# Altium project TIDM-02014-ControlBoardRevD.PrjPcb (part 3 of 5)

## Sheet thermal-management.SchDoc: Thermal Management
size 431 x 279 mm; Date: Not shown in title block; ApprovedBy: Not shown in title block; CheckedBy: Not shown in title block; Author: Not shown in title block; CompanyName: Not shown in title block; DrawnBy: Panacek; Engineer: Not shown in title block; Organization: Not shown in title block; Address1: Not shown in title block; Address2: Not shown in title block; Address3: Not shown in title block; Address4: Not shown in title block; DocumentNumber: 9; Revision: Use project parameter SCH_Rev; SheetNumber: 11; SheetTotal: 19; PageSetup: Record=PageOptions¦CenterHorizontal=True¦CenterVertical=True¦PrintScale=1.00¦XCorrection=1.00¦YCorrection=1.00¦PrintKind=0¦BorderSize=5000000¦LeftOffset=0¦BottomOffset=0¦Orientation=2¦PaperLength=1000¦PaperWidth=1000¦Scale=100¦PaperSource=15¦PrintQuality=600¦MediaType=1¦DitherType=10¦PaperKind=Letter¦PrintScaleMode=1
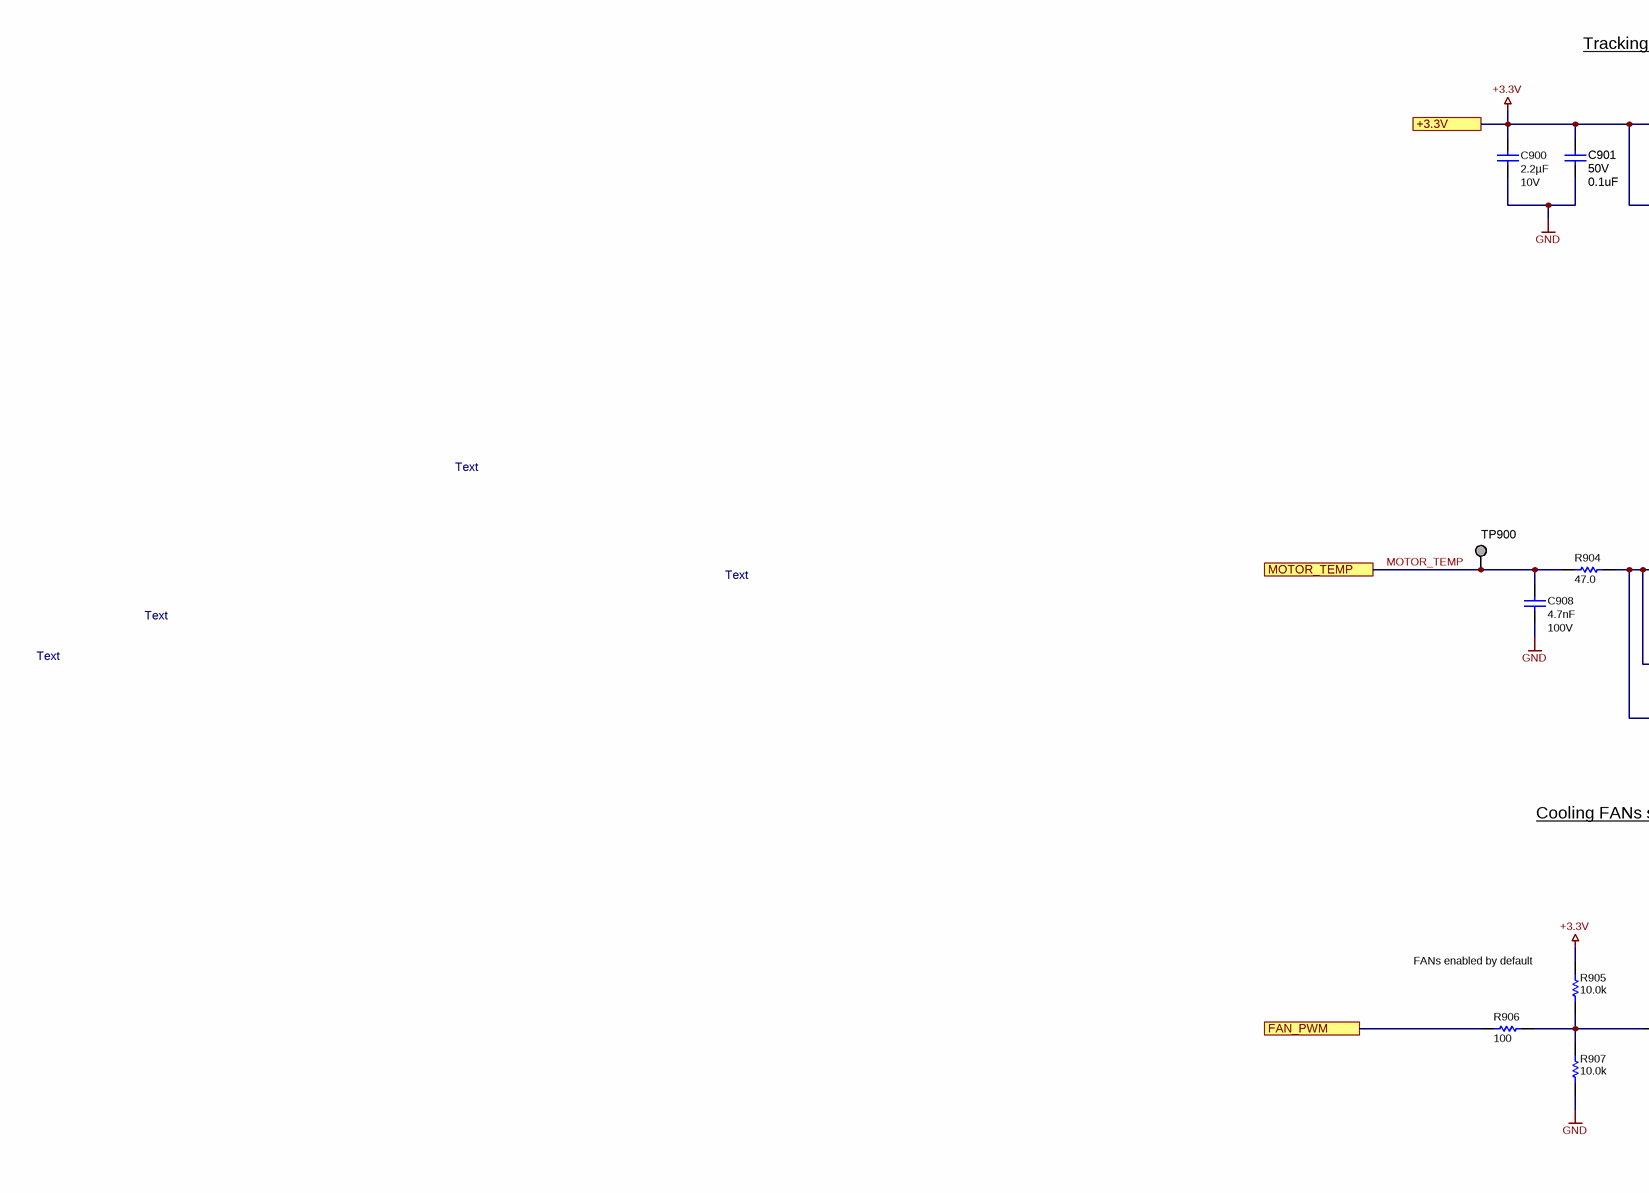
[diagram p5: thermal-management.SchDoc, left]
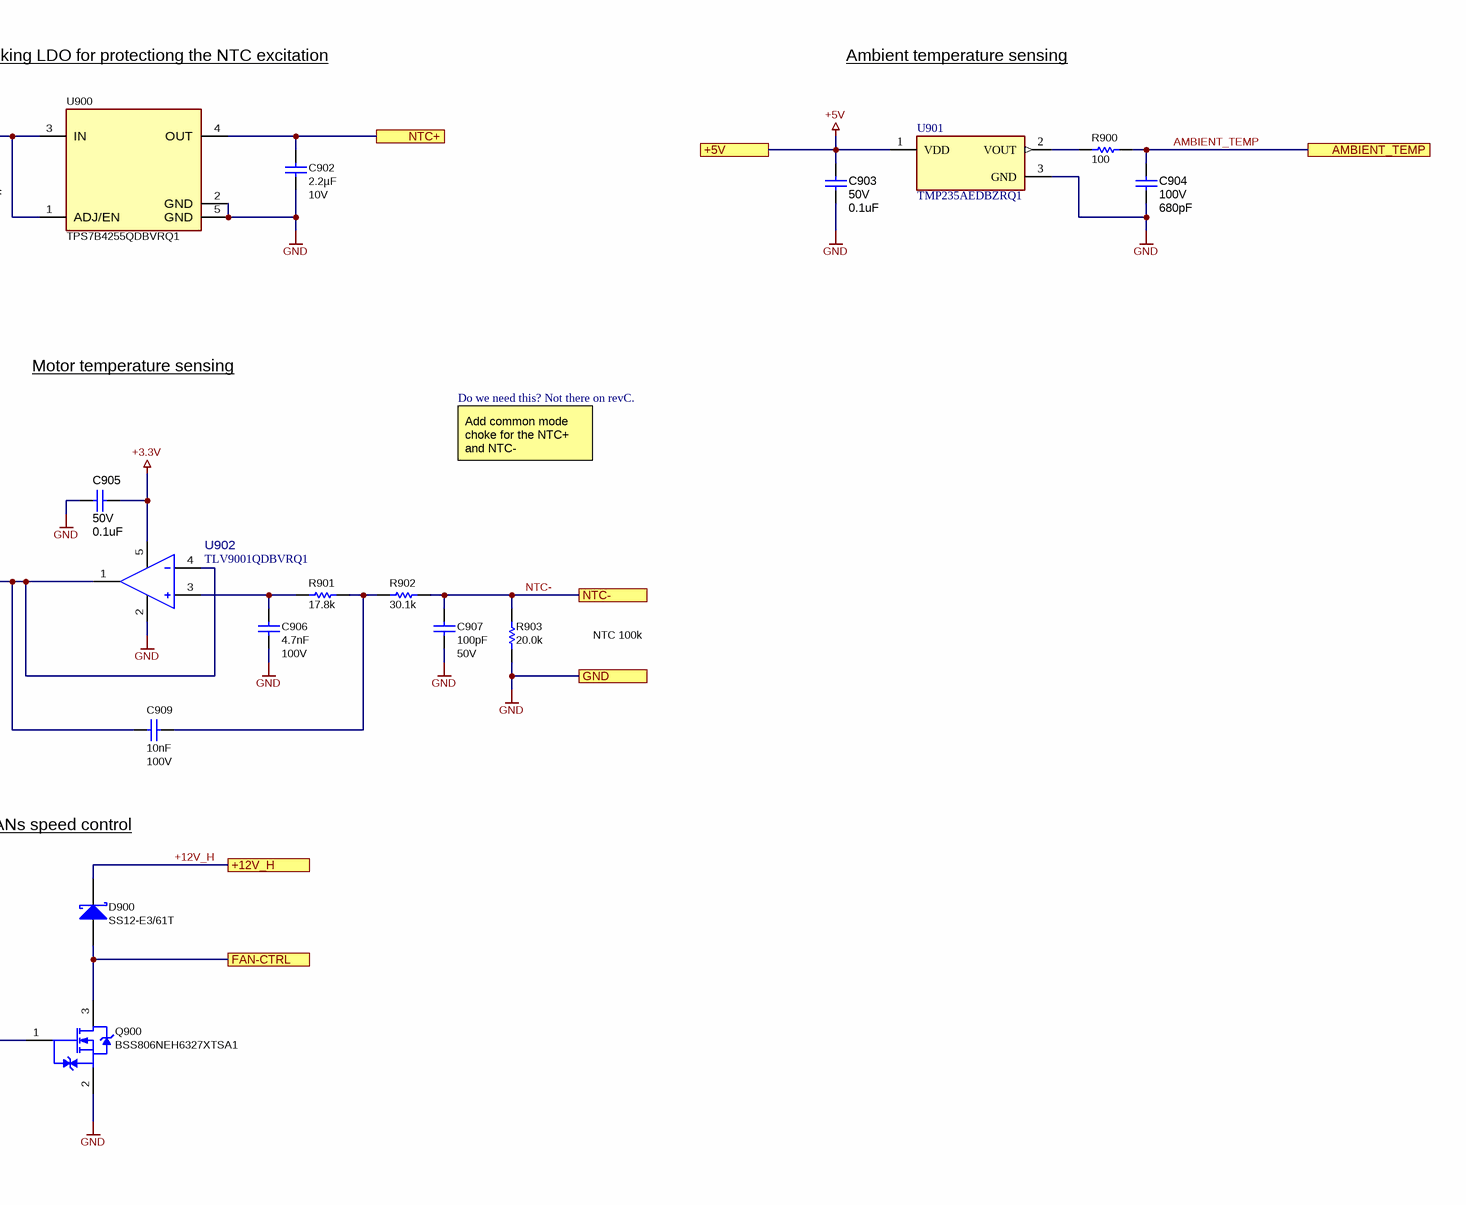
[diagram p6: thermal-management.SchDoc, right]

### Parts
C900  Cap_F: 2.2µF  VDC_V: 10V  [0603]  (hidden comment: GRM188R71A225KE15J)
C901  VDC_V: 50V  ValueDisplayed: 0.1uF  [0603]  (hidden comment: CGA3E2X7R1H104K080AA)
C902  Cap_F: 2.2µF  VDC_V: 10V  [0603]  (hidden comment: GRM188R71A225KE15J)
C903  VDC_V: 50V  ValueDisplayed: 0.1uF  [0603]  (hidden comment: CGA3E2X7R1H104K080AA)
C904  VDC_V: 100V  ValueDisplayed: 680pF  [0603]  (hidden comment: GRM188R72A681KA01D)
C905  VDC_V: 50V  ValueDisplayed: 0.1uF  [0603]  (hidden comment: CGA3E2X7R1H104K080AA)
C906  Cap_F: 4.7nF  VDC_V: 100V  [0603]  (hidden comment: GCM188R72A472KA37D)
C907  Cap_F: 100pF  VDC_V: 50V  [0603]  (hidden comment: CGA3E2NP01H101J080AA)
C908  Cap_F: 4.7nF  VDC_V: 100V  [0603]  (hidden comment: GCM188R72A472KA37D)
C909  Cap_F: 10nF  VDC_V: 100V  [0603]  (hidden comment: CGA3E2X7R2A103K080AA)
D900  SS12-E3/61T  [SMA]
Q900  BSS806NEH6327XTSA1  [SOT-23L]
R900  ValueDisplayed: 100  [0603]  (hidden comment: CRCW0603100RFKEA)
R901  ValueDisplayed: 17.8k  [0603]  (hidden comment: CRCW060317K8FKEA)
R902  ValueDisplayed: 30.1k  [0603]  (hidden comment: CRCW060330K1FKEA)
R903  ValueDisplayed: 20.0k  [0805_HV]  (hidden comment: CRCW080520K0FKEA)
R904  ValueDisplayed: 47.0  [0603]  (hidden comment: CRCW060347R0FKEA)
R905  ValueDisplayed: 10.0k  [0603]  (hidden comment: CRCW060310K0FKEA)
R906  ValueDisplayed: 100  [0603]  (hidden comment: CRCW0603100RFKEA)
R907  ValueDisplayed: 10.0k  [0603]  (hidden comment: CRCW060310K0FKEA)
TP900  RCU-0C  [TE_RCU]  (value not drawn)
U900  TPS7B4255QDBVRQ1  [DBV0005A-MFG]
U901  TMP235AEDBZRQ1  [FP-DBZ0003A-IPC_A]
U902  TLV9001QDBVRQ1  [DBV0005A-MFG]

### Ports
+3.3V, +5V, +12V_H, AMBIENT_TEMP, FAN-CTRL, FAN_PWM, GND, MOTOR_TEMP, NTC+, NTC-

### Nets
+3.3V: C900.1 C901.2 C905.2 R905.2 U900.1(ADJ/EN) U900.3(IN) U902.5(V+) ; port +3.3V
+5V: C903.1 U901.1(VDD) ; port +5V
+12V_H: D900.1(K) ; port +12V_H
GND: C900.2 C901.1 C902.2 C903.2 C904.2 C905.1 C906.2 C907.2 C908.2 Q900.2(S) R903.1 R907.1 U900.2(GND) U900.5(GND) U901.3(GND) U902.2(V-) ; port GND
AMBIENT_TEMP: C904.1 R900.2 ; port AMBIENT_TEMP
FAN-CTRL: D900.2(A) Q900.3(D) ; port FAN-CTRL
FAN_PWM: R906.1 ; port FAN_PWM
MOTOR_TEMP: C908.1 R904.1 TP900.1 ; port MOTOR_TEMP
NTC+: C902.1 U900.4(OUT) ; port NTC+
NTC-: C907.1 R902.2 R903.2 ; port NTC-
NetC906_1: C906.1 R901.1 U902.3(IN+)
NetC909_1: C909.1 R901.2 R902.1
NetC909_2: C909.2 R904.2 U902.1(OUT) U902.4(IN-)
NetQ900_1: Q900.1(G) R905.1 R906.2 R907.2
NetR900_1: R900.1 U901.2(VOUT)

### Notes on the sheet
- Tracking LDO for protectiong the NTC excitation
- Ambient temperature sensing
- Motor temperature sensing
- Do we need this? Not there on revC.
- Text
- Add common mode choke for the NTC+ and NTC-
- NTC 100k
- Cooling FANs speed control
- (near R905) FANs enabled by default

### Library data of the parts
C900 C902 = CMP-0084284-1: CAP, CERM, 2.2 µF, 10 V,+/- 10%, X7R, AEC-Q200 Grade 1, 0603; Manufacturer: MuRata; SizeAreaWB_mm2: 4.68; Polarized: N; AEC Qualified: Y; SizeX_mm: 1.6; SizeZ_mm: 1; SizeY_mm: 0.8; U/M: EA; TaMin_C: -55°C; Value: 2.2uF; AEC Category: Q200; TaMax_C: 125°C; SizeArea_mm2: 1.28
C901 C903 C905 = CMP-0007078-4: CAP, CERM, 0.1 uF, 50 V, +/- 10%, X7R, AEC-Q200 Grade 1, 0603; Manufacturer: TDK; TaMin_C: -55°C; Polarized: N; SizeAreaWB_mm2: 4.68; U/M: EA; Value: 0.1uF; TaMax_C: 125°C; SizeZ_mm: 1; SizeX_mm: 1.6; SizeY_mm: 0.8; SizeArea_mm2: 1.28; AEC Qualified: Y; Cap_F: 100nF; AEC Category: Q200; ESR_ohm: 29.6m; IRMS_A: 971.99mA; Value1: 0.0296 ohm
C904 = CMP-0007486-5: CAP, CERM, 680 pF, 100 V, +/- 10%, X7R, 0603; Manufacturer: MuRata; TaMin_C: -55°C; Polarized: N; SizeAreaWB_mm2: 4.68; Value1: Unknown; U/M: EA; Value: 680pF; TaMax_C: 125°C; SizeZ_mm: 1; SizeX_mm: 1.6; SizeY_mm: 0.8; SizeArea_mm2: 1.28; AEC Category: Q200
C906 C908 = CMP-0079247-1: CAP, CERM, 4700 pF, 100 V,+/- 10%, X7R, AEC-Q200 Grade 1, 0603; Manufacturer: MuRata; TaMin_C: -55°C; Polarized: N; SizeAreaWB_mm2: 4.68; U/M: EA; Value: 4700pF; TaMax_C: 125°C; SizeZ_mm: 1; SizeX_mm: 1.6; SizeY_mm: 0.8; SizeArea_mm2: 1.28; AEC Qualified: Y; AEC Category: Q200
C907 = CMP-0007075-4: CAP, CERM, 100 pF, 50 V, +/- 5%, C0G/NP0, AEC-Q200 Grade 0, 0603; Manufacturer: TDK; TaMin_C: -55°C; Polarized: N; SizeAreaWB_mm2: 4.68; Value1: Unknown; U/M: EA; Value: 100pF; TaMax_C: 150°C; SizeZ_mm: 1; SizeX_mm: 1.6; SizeY_mm: 0.8; SizeArea_mm2: 1.28; AEC Qualified: Y; AEC Grade: 0; AEC Category: Q200
C909 = CMP-0007082-4: CAP, CERM, 0.01 uF, 100 V, +/- 10%, X7R, AEC-Q200 Grade 1, 0603; Manufacturer: TDK; TaMin_C: -55°C; Polarized: N; SizeAreaWB_mm2: 4.68; Value1: 0.235428 ohm; U/M: EA; Value: 0.01uF; TaMax_C: 125°C; SizeZ_mm: 1; SizeX_mm: 1.6; SizeY_mm: 0.8; SizeArea_mm2: 1.28; AEC Qualified: Y; AEC Category: Q200; ESR_ohm: 0.2354; IRMS_A: 396.995mA
D900 = CMP-0028582-2: Diode, Schottky, 20 V, 1 A, SMA; Manufacturer: Vishay-Semiconductor; SizeZ_mm: 2.87; SizeX_mm: 5.59; Green_Lifecycle: Not Set; RJC_CperW: 28; Io_A: 1A; Green_REACh: Incomplete; Vr_V: 20V; AEC Category: Q101; TJmax_C: 125°C; Value2: 0.5V; SizeAreaWB_mm2: 37.3428; Value: 20V; SizeArea_mm2: 16.3228; Vf_V: 500mV; SizeY_mm: 2.92
Q900 = CMP-0077248-1: MOSFET, N-CH, 20 V, 2.3 A, AEC-Q101, SOT-23; Manufacturer: Infineon Technologies; Alternate Manufacturer: None; ChType: N; QgTyp_nC: 1.7; SizeAreaWB_mm2: 14.0; SizeArea_mm2: 7.5; IdsMax_A: 2.3A; AEC Qualified: Y; VdsMax_V: 20V; Vgs_V: 8V; AEC Category: Q101; Value: 20V; SizeZ_mm: 1.1; SizeY_mm: 3.0; Value2: 1.7 nC; U/M: EA; Value1: ? ohm; SizeX_mm: 2.5
R900 R906 = CMP-0021991-4: RES, 100, 1%, 0.1 W, AEC-Q200 Grade 0, 0603; Manufacturer: Vishay-Dale; Power_W: 100mW; TempCo: 100 ppm/C; Value_Code: 100R; Value: 100; EIA_Code: E96; SizeX_mm: 1.6; SizeY_mm: 0.8; SizeZ_mm: 1; Value2: 0.1W; SizeArea_mm2: 1.28; AEC Qualified: Y; VDC_V: 75V; AEC Category: Q200; AEC Grade: 0
R901 = CMP-0022090-4: RES, 17.8 k, 1%, 0.1 W, AEC-Q200 Grade 0, 0603; Manufacturer: Vishay-Dale; Power_W: 100mW; TempCo: 100 ppm/C; Value_Code: 17k8; Value: 17.8k; EIA_Code: E96; SizeX_mm: 1.6; SizeY_mm: 0.8; SizeZ_mm: 1; Value2: 0.1W; SizeArea_mm2: 1.28; AEC Qualified: Y; VDC_V: 75V; AEC Category: Q200; AEC Grade: 0
R902 = CMP-0022324-4: RES, 30.1 k, 1%, 0.1 W, AEC-Q200 Grade 0, 0603; Manufacturer: Vishay-Dale; Power_W: 100mW; TempCo: 100 ppm/C; Value_Code: 30k1; Value: 30.1k; EIA_Code: E96; SizeX_mm: 1.6; SizeY_mm: 0.8; SizeZ_mm: 1; Value2: 0.1W; SizeArea_mm2: 1.28; AEC Qualified: Y; VDC_V: 75V; AEC Category: Q200; AEC Grade: 0
R903 = CMP-0021042-3: RES, 20.0 k, 1%, 0.125 W, AEC-Q200 Grade 0, 0805; Manufacturer: Vishay-Dale; Power_W: 125mW; TempCo: 100 ppm/C; Value_Code: 20k0; Value: 20.0k; EIA_Code: E96; Res_ohm: 20k; SizeX_mm: 2; SizeY_mm: 1.25; SizeZ_mm: 1.45; Value2: 0.125W; SizeArea_mm2: 2.5; AEC Qualified: Y; VDC_V: 150V; AEC Category: Q200; AEC Grade: 0
R904 = CMP-0081280-1: RES, 47.0, 1%, 0.1 W, AEC-Q200 Grade 0, 0603; Manufacturer: Vishay-Dale; Value: 47.0; Res_ohm: 47; Value_Code: 47R0; Power_W: 100mW; Value2: 0.1W; VDC_V: 75V; TempCo: 100 ppm/C; SizeArea_mm2: 1.28; SizeX_mm: 1.6; SizeY_mm: 0.8; SizeZ_mm: 1; AEC Category: Q200; AEC Qualified: Y; AEC Grade: 0; SizeAreaWB_mm2: 4.68
R905 R907 = CMP-0021998-4: RES, 10.0 k, 1%, 0.1 W, AEC-Q200 Grade 0, 0603; Manufacturer: Vishay-Dale; Power_W: 100mW; TempCo: 100 ppm/C; Value_Code: 10k0; Value: 10.0k; EIA_Code: E96; Res_ohm: 10k; SizeX_mm: 1.6; SizeY_mm: 0.8; SizeZ_mm: 1; Value2: 0.1W; SizeArea_mm2: 1.28; AEC Qualified: Y; VDC_V: 75V; AEC Category: Q200; AEC Grade: 0
TP900 = CMP-0067620-1: PC Test Point, SMT; Manufacturer: TE Connectivity
U900 = CMP-0096536-1: Automotive, 70-mA, 40-V, Voltage-Tracking LDO With 5-mV Tracking Tolerance, SOT23-5; Manufacturer: Texas Instruments; SizeZ_mm: 1.45mm; Standoff Height: 0mm; Max Supply Voltage: 40V; TaMax_C: +125°C; Dropout Voltage: 500mV; AEC Qualified: Yes; Min Supply Voltage: 3V; Output Voltage: 2-40V; AEC Grade: Grade 1; Nominal Supply Current: 600-800uA; Number Of Outputs: 1; TaMin_C: -40°C; TJmax_C: +150°C; Output Type: AdjustableProgrammable
U901 = CMP-04948-000108-1: IC TEMP SENSOR; Manufacturer: Texas Instruments
U902 = CMP-0120546-1: Automotive, single-channel, 5.5-V 1-MHz rail-to-rail input and output operational amplifier 5-SOT-23 -40 to 125; Manufacturer: Texas Instruments; SizeZ_mm: 1.45mm; AEC Qualified: Yes; AEC Grade: Grade 1; Gain Bandwidth: 1MHz; Input Bias Current: 0.000005uA; Input Offset Voltage: 0.4mV; Max Dual Supply Voltage: 2.75V; Max Supply Voltage: 5.5V; Min Dual Supply Voltage: 900mV; Min Supply Voltage: 1.8V; Nominal Supply Current: 60uA; Number Of Channels: 1; Output Current Per Channel: 40mA; Response Time: 3us; Standoff Height: 0mm; TaMax_C: +125°C; TaMin_C: -40°C; TJmax_C: +150°C; Voltage Gain: 130dB

## Sheet hardware.SchDoc: Hardaware / Mechanical
size 431 x 279 mm; Date: Not shown in title block; ApprovedBy: Not shown in title block; CheckedBy: Not shown in title block; Author: Not shown in title block; CompanyName: Not shown in title block; DrawnBy: Panacek; Engineer: Not shown in title block; Organization: Not shown in title block; Address1: Not shown in title block; Address2: Not shown in title block; Address3: Not shown in title block; Address4: Not shown in title block; DocumentNumber: 12; Revision: Use project parameter SCH_Rev; SheetNumber: 14; SheetTotal: 19; PageSetup: Record=PageOptions¦CenterHorizontal=True¦CenterVertical=True¦PrintScale=1.00¦XCorrection=1.00¦YCorrection=1.00¦PrintKind=0¦BorderSize=5000000¦LeftOffset=0¦BottomOffset=0¦Orientation=2¦PaperLength=1000¦PaperWidth=1000¦Scale=100¦PaperSource=15¦PrintQuality=600¦MediaType=1¦DitherType=10¦PaperKind=Letter¦PrintScaleMode=1
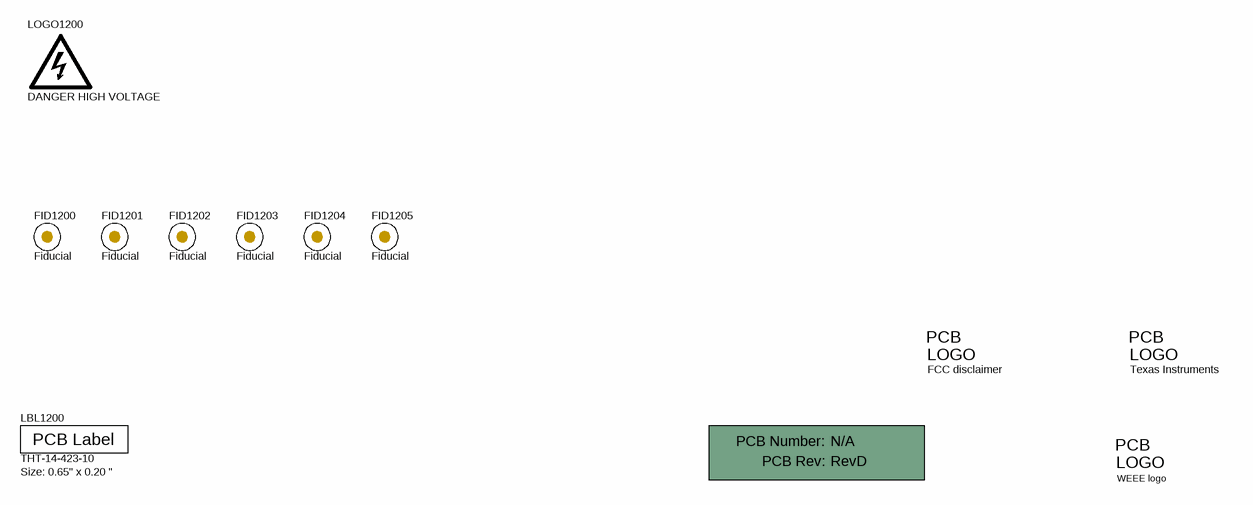
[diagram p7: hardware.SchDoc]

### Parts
!PCB1200  Printed Circuit Board  (value not drawn)  (mechanical)
FID1200  Fiducial  [Fiducial10-20]
FID1201  Fiducial  [Fiducial10-20]
FID1202  Fiducial  [Fiducial10-20]
FID1203  Fiducial  [Fiducial10-20]
FID1204  Fiducial  [Fiducial10-20]
FID1205  Fiducial  [Fiducial10-20]
LBL1200  THT-14-423-10  Note: Size: 0.65" x 0.20 "  [Label_650x200]
LOGO1200  DANGER HIGH VOLTAGE  [IEC_HighVoltage_Large]  (no BOM)
Logo1201  FCC disclaimer  [FCC_disclaimer]  (no BOM)
Logo1202  Texas Instruments  [TI_Stacked_Overlay_Small]  (no BOM)
Logo1203  WEEE logo  [WEEE_Minimum]  (no BOM)

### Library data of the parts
!PCB1200 = CMP-0003618-2: Manufacturer: Any
FID1200-FID1205 = CMP-0077181-1: Fiducial mark.  There is nothing to buy or mount.
LBL1200 = CMP-0003625-1: Thermal Transfer Printable Labels, 0.650" W x 0.200" H - 10,000 per roll; Manufacturer: Brady
LOGO1200 = CMP-0074835-1: IEC 61010-1 High Voltage Warning; SymbolCreator: a0412235
Logo1201 = CMP-0074847-1: FCC_disclaimer
Logo1202 = CMP-0074838-1: Texas Instrument Corporate Signature; SymbolCreator: a0412235; Lib Reference: TI_Logo
Logo1203 = CMP-0074769-1

## Sheet eqep_ecap_interface.SchDoc: EQEO/ECAP Inaterface
size 431 x 279 mm; Date: Not shown in title block; ApprovedBy: Not shown in title block; CheckedBy: Not shown in title block; Author: Not shown in title block; CompanyName: Not shown in title block; DrawnBy: Panacek; Engineer: Not shown in title block; Organization: Not shown in title block; Address1: Not shown in title block; Address2: Not shown in title block; Address3: Not shown in title block; Address4: Not shown in title block; DocumentNumber: 11; Revision: Use project parameter SCH_Rev; SheetNumber: 13; SheetTotal: 19; PageSetup: Record=PageOptions¦CenterHorizontal=True¦CenterVertical=True¦PrintScale=1.00¦XCorrection=1.00¦YCorrection=1.00¦PrintKind=0¦BorderSize=5000000¦LeftOffset=0¦BottomOffset=0¦Orientation=2¦PaperLength=1000¦PaperWidth=1000¦Scale=100¦PaperSource=15¦PrintQuality=600¦MediaType=1¦DitherType=10¦PaperKind=Letter¦PrintScaleMode=1
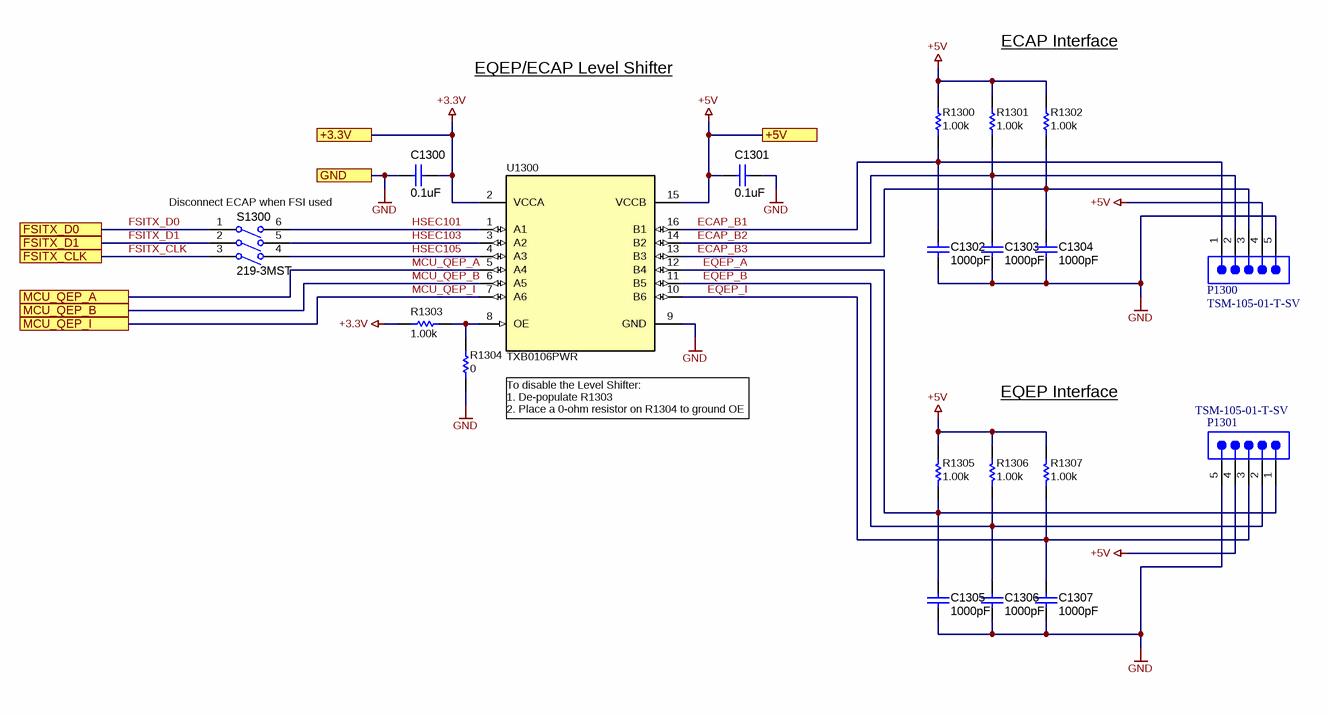
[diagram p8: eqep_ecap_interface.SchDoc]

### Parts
C1300  ValueDisplayed: 0.1uF  [0603]  (hidden comment: CGA3E2X7R1H104K080AA)
C1301  ValueDisplayed: 0.1uF  [0603]  (hidden comment: CGA3E2X7R1H104K080AA)
C1302  ValueDisplayed: 1000pF  [0603]  (hidden comment: GRM1885C1H102JA01D)
C1303  ValueDisplayed: 1000pF  [0603]  (hidden comment: GRM1885C1H102JA01D)
C1304  ValueDisplayed: 1000pF  [0603]  (hidden comment: GRM1885C1H102JA01D)
C1305  ValueDisplayed: 1000pF  [0603]  (hidden comment: GRM1885C1H102JA01D)
C1306  ValueDisplayed: 1000pF  [0603]  (hidden comment: GRM1885C1H102JA01D)
C1307  ValueDisplayed: 1000pF  [0603]  (hidden comment: GRM1885C1H102JA01D)
P1300  TSM-105-01-T-SV  [SMTC-TSM-105-01-X-SV]
P1301  TSM-105-01-T-SV  [SMTC-TSM-105-01-X-SV]
R1300  ValueDisplayed: 1.00k  [0603]  (hidden comment: CRCW06031K00FKEA)
R1301  ValueDisplayed: 1.00k  [0603]  (hidden comment: CRCW06031K00FKEA)
R1302  ValueDisplayed: 1.00k  [0603]  (hidden comment: CRCW06031K00FKEA)
R1303  ValueDisplayed: 1.00k  [0603]  (hidden comment: CRCW06031K00FKEA)
R1304  ValueDisplayed: 0  [0603]  (hidden comment: CRCW06030000Z0EA)
R1305  ValueDisplayed: 1.00k  [0603]  (hidden comment: CRCW06031K00FKEA)
R1306  ValueDisplayed: 1.00k  [0603]  (hidden comment: CRCW06031K00FKEA)
R1307  ValueDisplayed: 1.00k  [0603]  (hidden comment: CRCW06031K00FKEA)
S1300  219-3MST  [SW_219-3MST]
U1300  TXB0106PWR  [PW0016A_N]

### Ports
+3.3V, +5V, FSITX_CLK, FSITX_D0, FSITX_D1, GND, MCU_QEP_A, MCU_QEP_B, MCU_QEP_I

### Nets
+3.3V: C1300.1 R1303.1 U1300.2(VCCA) ; port +3.3V
+5V: C1301.2 P1300.4 P1301.4 R1300.2 R1301.2 R1302.2 R1305.2 R1306.2 R1307.2 U1300.15(VCCB) ; port +5V
GND: C1300.2 C1301.1 C1302.2 C1303.2 C1304.2 C1305.2 C1306.2 C1307.2 P1300.5 P1301.5 R1304.1 U1300.9(GND) ; port GND
ECAP_B1: C1302.1 P1300.1 R1300.1 U1300.16(B1)  [project net ECAP_B1_13]
ECAP_B2: C1303.1 P1300.2 R1301.1 U1300.14(B2)  [project net ECAP_B2_13]
ECAP_B3: C1304.1 P1300.3 R1302.1 U1300.13(B3)  [project net ECAP_B3_13]
EQEP_A: C1305.1 P1301.1 R1305.1 U1300.12(B4)  [project net EQEP_A_13]
EQEP_B: C1306.1 P1301.2 R1306.1 U1300.11(B5)  [project net EQEP_B_13]
EQEP_I: C1307.1 P1301.3 R1307.1 U1300.10(B6)  [project net EQEP_I_13]
FSITX_CLK: S1300.3(A3) ; port FSITX_CLK
FSITX_D0: S1300.1(A1) ; port FSITX_D0
FSITX_D1: S1300.2(A2) ; port FSITX_D1
HSEC101: S1300.6(B1) U1300.1(A1)  [project net HSEC101_13]
HSEC103: S1300.5(B2) U1300.3(A2)  [project net HSEC103_13]
HSEC105: S1300.4(B3) U1300.4(A3)  [project net HSEC105_13]
MCU_QEP_A: U1300.5(A4) ; port MCU_QEP_A
MCU_QEP_B: U1300.6(A5) ; port MCU_QEP_B
MCU_QEP_I: U1300.7(A6) ; port MCU_QEP_I
NetR1303_2: R1303.2 R1304.2 U1300.8(OE)

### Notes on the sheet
- ECAP Interface
- EQEP/ECAP Level Shifter
- (near S1300) Disconnect ECAP when FSI used
- To disable the Level Shifter:
  1. De-populate R1303
  2. Place a 0-ohm resistor on R1304 to ground OE
- EQEP Interface

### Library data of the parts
C1300 C1301 = CMP-0007078-4: CAP, CERM, 0.1 uF, 50 V, +/- 10%, X7R, AEC-Q200 Grade 1, 0603; Manufacturer: TDK; Polarized: N; Value: 0.1uF; U/M: EA; Cap_F: 100nF; ESR_ohm: 29.6m; Value1: 0.0296 ohm; VDC_V: 50V; IRMS_A: 971.99mA; TaMin_C: -55°C; TaMax_C: 125°C; SizeArea_mm2: 1.28; SizeAreaWB_mm2: 4.68; SizeX_mm: 1.6; SizeY_mm: 0.8; SizeZ_mm: 1; AEC Category: Q200; AEC Qualified: Y
C1302-C1307 = CMP-0007173-4: CAP, CERM, 1000 pF, 50 V, +/- 5%, C0G/NP0, 0603; Manufacturer: MuRata; Polarized: N; Value: 1000pF; U/M: EA; Cap_F: 1nF; Value1: Unknown; VDC_V: 50V; TaMin_C: -55°C; TaMax_C: 125°C; SizeArea_mm2: 1.28; SizeAreaWB_mm2: 4.68; SizeX_mm: 1.6; SizeY_mm: 0.8; SizeZ_mm: 1; AEC Category: Q200
P1300 P1301 = CMP-1024-00239-1: 0.025" SQ Post Header, Surface Mount, Vertical, -55 to 105 degC, 2.54 mm Pitch, 5-Pin, Male, RoHS; Manufacturer: Samtec; Pitch: 2.54 mm
R1300-R1303 R1305-R1307 = CMP-0022109-5: RES, 1.00 k, 1%, 0.1 W, AEC-Q200 Grade 0, 0603; Manufacturer: Vishay-Dale; Value: 1.00k; Res_ohm: 1k; Value_Code: 1k00; Power_W: 100mW; Value2: 0.1W; VDC_V: 75V; TempCo: 100 ppm/C; SizeArea_mm2: 1.28; SizeX_mm: 1.6; SizeY_mm: 0.8; SizeZ_mm: 1; EIA_Code: E96; AEC Category: Q200; AEC Qualified: Y; AEC Grade: 0
R1304 = CMP-0025697-4: RES, 0, 5%, 0.1 W, AEC-Q200 Grade 0, 0603; Manufacturer: Vishay-Dale; Value: 0; Value_Code: 0000; Power_W: 100mW; Value2: 0.1W; VDC_V: 75V; TempCo: 200 ppm/C; SizeArea_mm2: 1.28; SizeX_mm: 1.6; SizeY_mm: 0.8; SizeZ_mm: 1; EIA_Code: E24; AEC Category: Q200; AEC Qualified: Y
S1300 = CMP-0002269-1: Switch, SPST, Slide, Off-On, 3 Pos, 0.1A, 20V, SMD; Manufacturer: CTS Electrocomponents; CurrentRating_mA: 100A; PositionCount: 3
U1300 = CMP-0067443-1: 6-Bit Bidirectional Voltage-Level Translator with Auto Direction Sensing and +/-15-kV ESD Protect, PW0016A (TSSOP-16); Manufacturer: Texas Instruments; SizeArea_mm2: 32.0; SizeAreaWB_mm2: 58.8; SizeX_mm: 6.4; SizeY_mm: 5.0; SizeZ_mm: 1.2; CompType: IC; U/M: EA; Green_Lifecycle: Active; Green_REACh: Passed

## Sheet Current Sense Connector.SchDoc
size 431 x 279 mm; Date: Not shown in title block; ApprovedBy: Not shown in title block; CheckedBy: Not shown in title block; Author: Not shown in title block; CompanyName: Not shown in title block; Engineer: Not shown in title block; Organization: Not shown in title block; Address1: Not shown in title block; Address2: Not shown in title block; Address3: Not shown in title block; Address4: Not shown in title block; DocumentNumber: 15; Revision: Use project parameter SCH_Rev; SheetNumber: 15; SheetTotal: 19; PageSetup: Record=PageOptions¦CenterHorizontal=True¦CenterVertical=True¦PrintScale=1.00¦XCorrection=1.00¦YCorrection=1.00¦PrintKind=0¦BorderSize=5000000¦LeftOffset=0¦BottomOffset=0¦Orientation=2¦PaperLength=1000¦PaperWidth=1000¦Scale=100¦PaperSource=15¦PrintQuality=600¦MediaType=1¦DitherType=10¦PaperKind=Letter¦PrintScaleMode=1
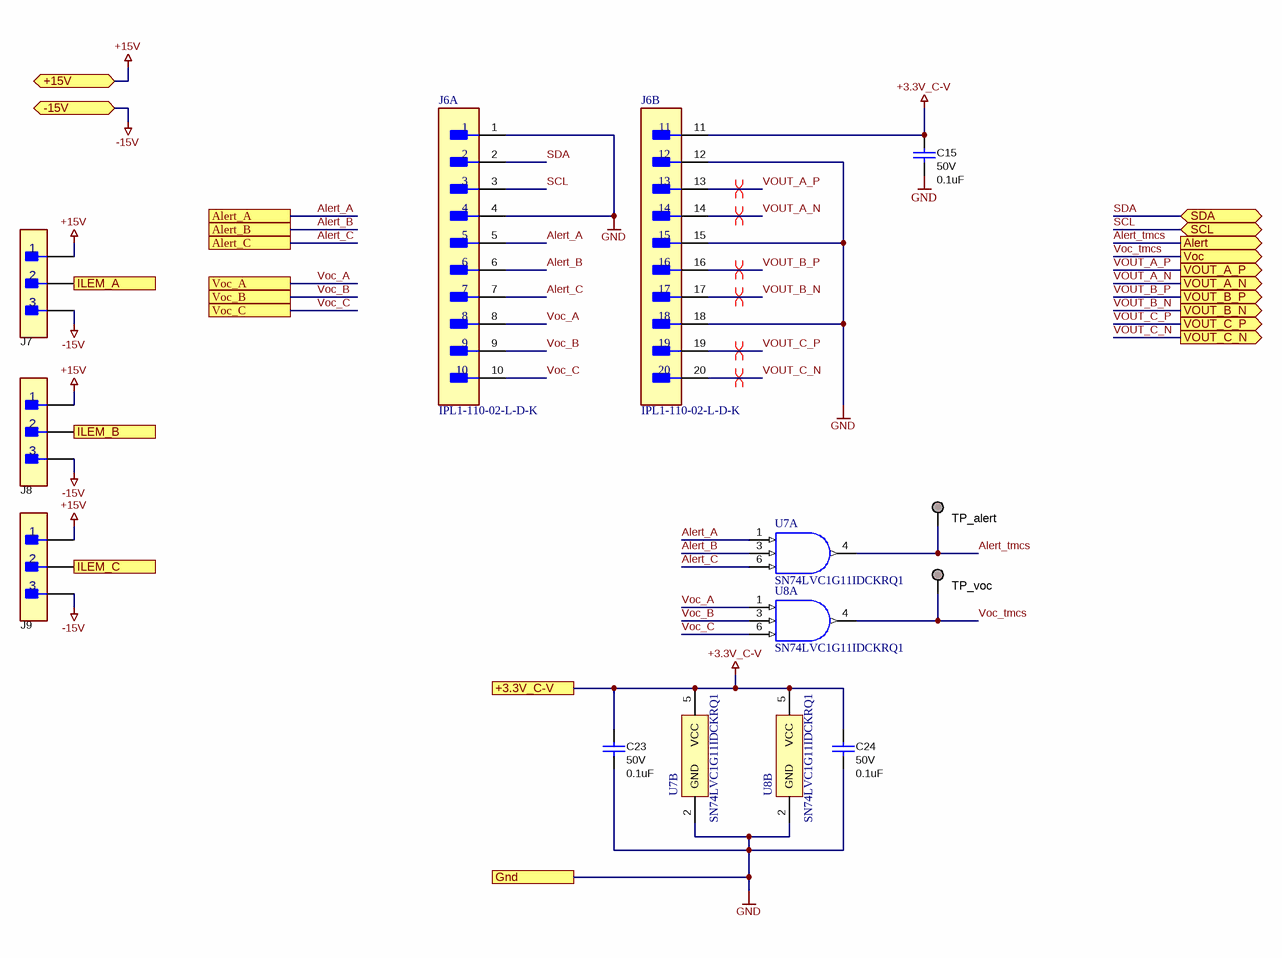
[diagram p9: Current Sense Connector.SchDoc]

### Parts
C15  VDC_V: 50V  ValueDisplayed: 0.1uF  [0603]  (hidden comment: CGA3E2X7R1H104K080AA)
C23  VDC_V: 50V  ValueDisplayed: 0.1uF  [0603]  (hidden comment: CGA3E2X7R1H104K080AA)
C24  VDC_V: 50V  ValueDisplayed: 0.1uF  [0603]  (hidden comment: CGA3E2X7R1H104K080AA)
J6  IPL1-110-02-L-D-K  [FP-IPL1-110-02-L-D-K-0]  (parts A,B of 2)
J7  22232031  [FP-22232031_HDR3-MFG]  (value not drawn)
J8  22232031  [FP-22232031_HDR3-MFG]  (value not drawn)
J9  22232031  [FP-22232031_HDR3-MFG]  (value not drawn)
TP_alert  RCU-0C  [TE_RCU]  (value not drawn)
TP_voc  RCU-0C  [TE_RCU]  (value not drawn)
U7  SN74LVC1G11IDCKRQ1  [DCK0006A_N]  (parts A,B of 2)
U8  SN74LVC1G11IDCKRQ1  [DCK0006A_N]  (parts A,B of 2)

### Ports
+3.3V_C-V, +15V (bidir), -15V (bidir), Alert (out), Alert_A, Alert_B, Alert_C, Gnd, ILEM_A (out), ILEM_B (out), ILEM_C (out), SCL (bidir), SDA (bidir), Voc (out), Voc_A, Voc_B, Voc_C, VOUT_A_N (out), VOUT_A_P (out), VOUT_B_N (out), VOUT_B_P (out), VOUT_C_N (out), VOUT_C_P (out)

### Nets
+3.3V_C-V: C15.1 C23.1 C24.1 J6.11 U7.5(VCC) U8.5(VCC) ; port +3.3V_C-V
+15V: J7.1 J8.1 J9.1 ; port +15V
-15V: J7.3 J8.3 J9.3 ; port -15V
GND: C15.2 C23.2 C24.2 J6.1 J6.4 J6.12 J6.15 J6.18 U7.2(GND) U8.2(GND) ; port Gnd
Alert_A: J6.5 U7.1(A) ; port Alert_A
Alert_B: J6.6 U7.3(B) ; port Alert_B
Alert_C: J6.7 U7.6(C) ; port Alert_C
Alert_tmcs: TP_alert.1 U7.4(Y) ; port Alert
ILEM_A: J7.2 ; port ILEM_A
ILEM_B: J8.2 ; port ILEM_B
ILEM_B: J9.2 ; port ILEM_C  [a separate net that carries the same name]
SCL: J6.3 ; port SCL  [project net IFB_I2C_SCL]
SDA: J6.2 ; port SDA  [project net IFB_I2C_SDA]
Voc_A: J6.8 U8.1(A) ; port Voc_A  [project net IFB_VOC_U]
Voc_B: J6.9 U8.3(B) ; port Voc_B  [project net IFB_VOC_W]
Voc_C: J6.10 U8.6(C) ; port Voc_C  [project net IFB_VOC_V]
Voc_tmcs: TP_voc.1 U8.4(Y) ; port Voc
VOUT_A_N: J6.14 ; port VOUT_A_N  [project net U_N]
VOUT_A_P: J6.13 ; port VOUT_A_P  [project net U_P]
VOUT_B_N: J6.17 ; port VOUT_B_N  [project net V_N]
VOUT_B_P: J6.16 ; port VOUT_B_P  [project net V_P]
VOUT_C_N: J6.20 ; port VOUT_C_N
VOUT_C_P: J6.19 ; port VOUT_C_P

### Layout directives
differential pair: U_N, U_P, V_N, V_P, VOUT_C_N, VOUT_C_P

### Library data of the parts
C15 C23 C24 = CMP-0007078-4: CAP, CERM, 0.1 uF, 50 V, +/- 10%, X7R, AEC-Q200 Grade 1, 0603; Manufacturer: TDK; TaMin_C: -55°C; ESR_ohm: 29.6m; Polarized: N; SizeAreaWB_mm2: 4.68; Value1: 0.0296 ohm; U/M: EA; Value: 0.1uF; TaMax_C: 125°C; SizeZ_mm: 1; SizeX_mm: 1.6; SizeY_mm: 0.8; SizeArea_mm2: 1.28; AEC Qualified: Y; Cap_F: 100nF; IRMS_A: 971.99mA; AEC Category: Q200
J6 = CMP-02766-000359-1: 10 Position 2 Row .100" (2.54 mm) pitch connector; Manufacturer: Samtec; Pitch: 2.54mm; Number of Contacts: 20; Max Voltage Rating (AC): 675V; Max Current Rating: 7.4A; Gender: Male; Number of Ports: 1
J7-J9 = CMP-0092858-1: Connector Header Through Hole 3 position 0.100" (2.54mm); Manufacturer: Molex; ContactFinish: Tin,Nickel; AEC Qualified: No; Conn Orientation: Vertical; Conn Gender: Male; Current_A: 4A; SizeZ_mm: 11.3mm; Row_Count: 1; Voltage_V: 500V
TP_alert TP_voc = CMP-0067620-1: as TP900 on sheet thermal-management
U7 U8 = CMP-0051218-3: Automotive Catalog Single 3-Input Positive-AND Gate, DCK0006A (SOT-SC70-6); Manufacturer: Texas Instruments; Generic Part Number: SN74LVC1G11-Q1; Output Type: CMOS; Bits(#): 1; Input Type: CMOS/TTL; Technology Family: LVC; Schmitt Trigger: No; VCC(Max)(V): 5.5; Gate Type: AND; Output Drive (IOL/IOH)(Max)(mA): 32/-32; ICC @ Nom Voltage(Max)(mA): 0.01; VCC(Min)(V): 1.65; F @ Nom Voltage(Max)(Mhz): 150; Logic: True; Voltage(Nom)(V): 1.8,2.5,3.3,5; tpd @ Nom Voltage(Max)(ns): 17.2,6.9,4.9,3.5; AEC Category: Q200; AEC Qualified: Y; CompType: IC; SizeAreaWB_mm2: 9.3; SizeArea_mm2: 4.2; SizeX_mm: 2.1; SizeY_mm: 2.0; SizeZ_mm: 1.1

## Sheet gd-interface.SchDoc: GD Interface
size 431 x 279 mm; Date: Not shown in title block; ApprovedBy: Not shown in title block; CheckedBy: Not shown in title block; Author: Not shown in title block; CompanyName: Not shown in title block; DrawnBy: Panacek; Engineer: Not shown in title block; Organization: Not shown in title block; Address1: Not shown in title block; Address2: Not shown in title block; Address3: Not shown in title block; Address4: Not shown in title block; DocumentNumber: 10; Revision: Use project parameter SCH_Rev; SheetNumber: 12; SheetTotal: 19; PageSetup: Record=PageOptions¦CenterHorizontal=True¦CenterVertical=True¦PrintScale=1.00¦XCorrection=1.00¦YCorrection=1.00¦PrintKind=0¦BorderSize=5000000¦LeftOffset=0¦BottomOffset=0¦Orientation=2¦PaperLength=1000¦PaperWidth=1000¦Scale=100¦PaperSource=15¦PrintQuality=600¦MediaType=1¦DitherType=10¦PaperKind=Letter¦PrintScaleMode=1
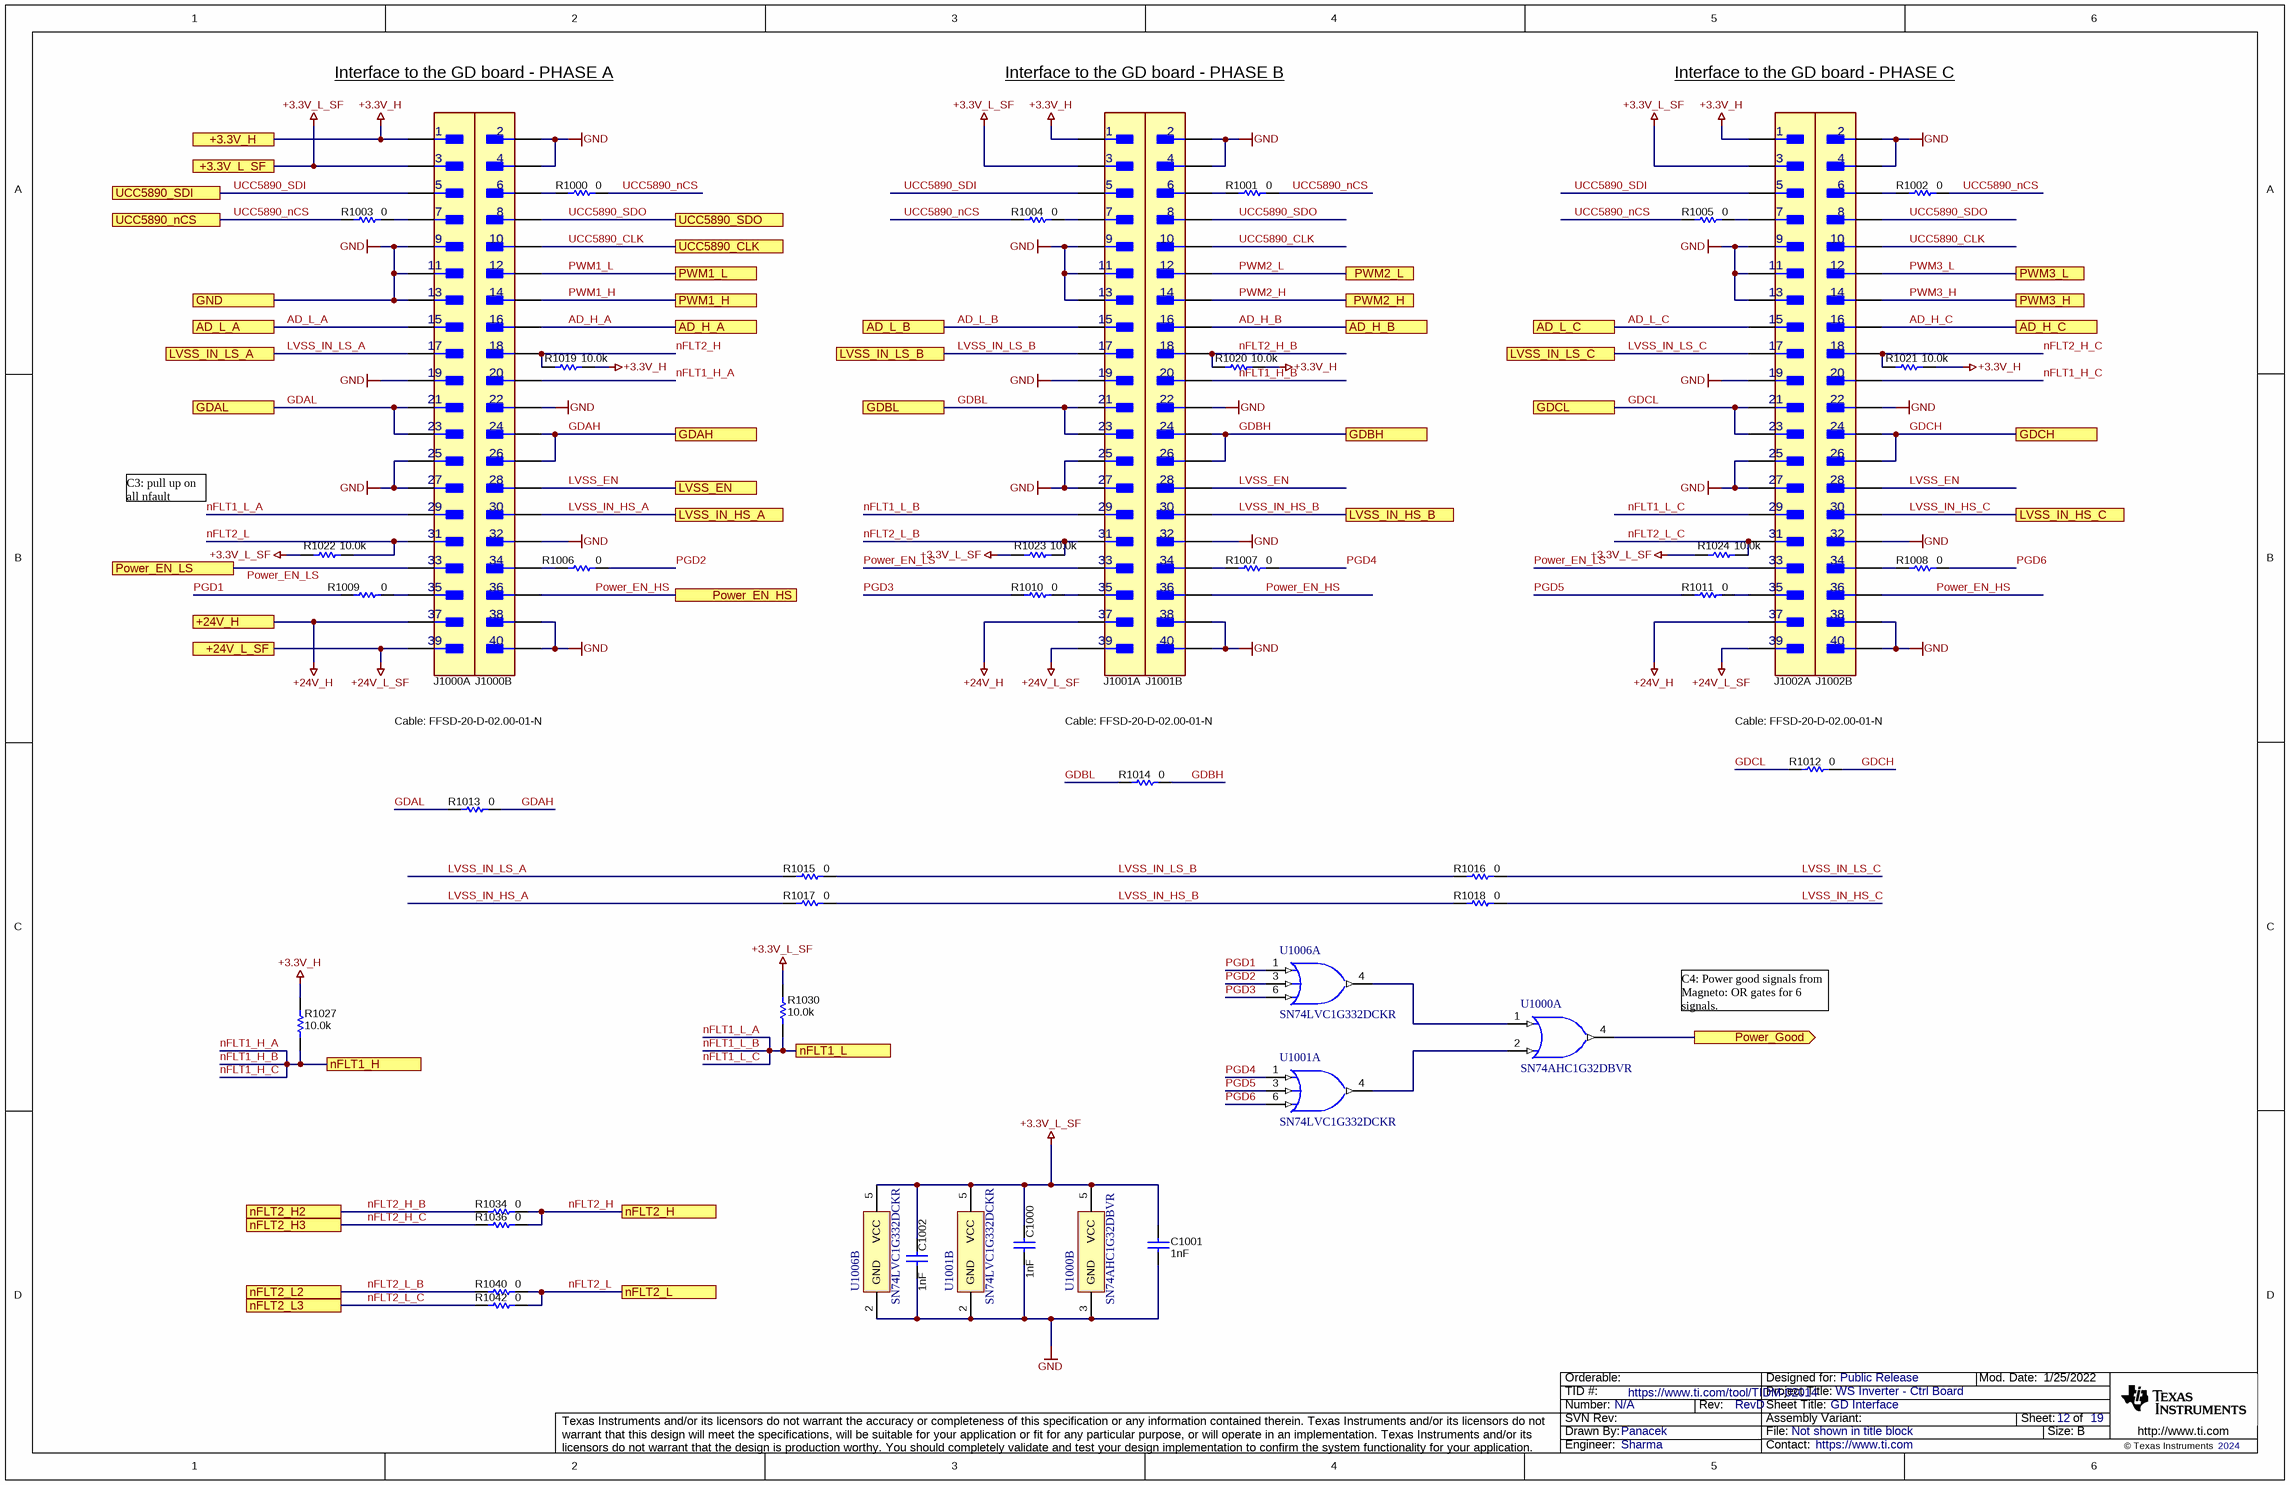
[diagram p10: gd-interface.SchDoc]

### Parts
C1000  Cap_F: 1nF  [0603]  (hidden comment: GRM1885C1H102JA01D)
C1001  Cap_F: 1nF  [0603]  (hidden comment: GRM1885C1H102JA01D)
C1002  Cap_F: 1nF  [0603]  (hidden comment: GRM1885C1H102JA01D)
J1000  ESHF-120-01-L-D-SM  [FP-ESHF-120-01-L-D-SM_HDR40-MFG]  (value not drawn)  (parts A,B of 2)
J1001  ESHF-120-01-L-D-SM  [FP-ESHF-120-01-L-D-SM_HDR40-MFG]  (value not drawn)  (parts A,B of 2)
J1002  ESHF-120-01-L-D-SM  [FP-ESHF-120-01-L-D-SM_HDR40-MFG]  (value not drawn)  (parts A,B of 2)
R1000  ValueDisplayed: 0  [0603]  (hidden comment: CRCW06030000Z0EA)
R1001  ValueDisplayed: 0  [0603]  (hidden comment: CRCW06030000Z0EA)
R1002  ValueDisplayed: 0  [0603]  (hidden comment: CRCW06030000Z0EA)
R1003  ValueDisplayed: 0  [0603]  (hidden comment: CRCW06030000Z0EA)
R1004  ValueDisplayed: 0  [0603]  (hidden comment: CRCW06030000Z0EA)
R1005  ValueDisplayed: 0  [0603]  (hidden comment: CRCW06030000Z0EA)
R1006  ValueDisplayed: 0  [0603]  (hidden comment: CRCW06030000Z0EA)
R1007  ValueDisplayed: 0  [0603]  (hidden comment: CRCW06030000Z0EA)
R1008  ValueDisplayed: 0  [0603]  (hidden comment: CRCW06030000Z0EA)
R1009  ValueDisplayed: 0  [0603]  (hidden comment: CRCW06030000Z0EA)
R1010  ValueDisplayed: 0  [0603]  (hidden comment: CRCW06030000Z0EA)
R1011  ValueDisplayed: 0  [0603]  (hidden comment: CRCW06030000Z0EA)
R1012  ValueDisplayed: 0  [0603]  (hidden comment: CRCW06030000Z0EA)
R1013  ValueDisplayed: 0  [0603]  (hidden comment: CRCW06030000Z0EA)
R1014  ValueDisplayed: 0  [0603]  (hidden comment: CRCW06030000Z0EA)
R1015  ValueDisplayed: 0  [0603]  (hidden comment: CRCW06030000Z0EA)
R1016  ValueDisplayed: 0  [0603]  (hidden comment: CRCW06030000Z0EA)
R1017  ValueDisplayed: 0  [0603]  (hidden comment: CRCW06030000Z0EA)
R1018  ValueDisplayed: 0  [0603]  (hidden comment: CRCW06030000Z0EA)
R1019  ValueDisplayed: 10.0k  [0603]  (hidden comment: CRCW060310K0FKEA)
R1020  ValueDisplayed: 10.0k  [0603]  (hidden comment: CRCW060310K0FKEA)
R1021  ValueDisplayed: 10.0k  [0603]  (hidden comment: CRCW060310K0FKEA)
R1022  ValueDisplayed: 10.0k  [0603]  (hidden comment: CRCW060310K0FKEA)
R1023  ValueDisplayed: 10.0k  [0603]  (hidden comment: CRCW060310K0FKEA)
R1024  ValueDisplayed: 10.0k  [0603]  (hidden comment: CRCW060310K0FKEA)
R1027  ValueDisplayed: 10.0k  [0603]  (hidden comment: CRCW060310K0FKEA)
R1030  ValueDisplayed: 10.0k  [0603]  (hidden comment: CRCW060310K0FKEA)
R1034  ValueDisplayed: 0  [0603]  (hidden comment: CRCW06030000Z0EA)
R1036  ValueDisplayed: 0  [0603]  (hidden comment: CRCW06030000Z0EA)
R1040  ValueDisplayed: 0  [0603]  (hidden comment: CRCW06030000Z0EA)
R1042  ValueDisplayed: 0  [0603]  (hidden comment: CRCW06030000Z0EA)
U1000  SN74AHC1G32DBVR  [DBV0005A_N]  (parts A,B of 2)
U1001  SN74LVC1G332DCKR  [DCK0006A_N]  (parts A,B of 2)
U1006  SN74LVC1G332DCKR  [DCK0006A_N]  (parts A,B of 2)

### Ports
+3.3V_H, +3.3V_L_SF, +24V_H, +24V_L_SF, AD_H_A, AD_H_B, AD_H_C, AD_L_A, AD_L_B, AD_L_C, GDAH, GDAL, GDBH, GDBL, GDCH, GDCL, GND, LVSS_EN, LVSS_IN_HS_A, LVSS_IN_HS_B, LVSS_IN_HS_C, LVSS_IN_LS_A, LVSS_IN_LS_B, LVSS_IN_LS_C, nFLT1_H, nFLT1_L, nFLT2_H, nFLT2_H2, nFLT2_H3, nFLT2_L, nFLT2_L2, nFLT2_L3, Power_EN_HS, Power_EN_LS, Power_Good (out), PWM1_H, PWM1_L, PWM2_H, PWM2_L, PWM3_H, PWM3_L, UCC5890_CLK, UCC5890_nCS, UCC5890_SDI, UCC5890_SDO

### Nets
+3.3V_H: J1000.1 J1001.1 J1002.1 R1019.2 R1020.2 R1021.2 R1027.1 ; port +3.3V_H
+3.3V_L_SF: C1000.2 C1001.2 C1002.2 J1000.3 J1001.3 J1002.3 R1022.1 R1023.1 R1024.1 R1030.1 U1000.5(VCC) U1001.5(VCC) U1006.5(VCC) ; port +3.3V_L_SF
+24V_H: J1000.37 J1001.37 J1002.37 ; port +24V_H
+24V_L_SF: J1000.39 J1001.39 J1002.39 ; port +24V_L_SF
GND: C1000.1 C1001.1 C1002.1 J1000.2 J1000.4 J1000.9 J1000.11 J1000.13 J1000.19 J1000.22 J1000.25 J1000.27 J1000.32 J1000.38 J1000.40 J1001.2 J1001.4 J1001.9 J1001.11 J1001.13 J1001.19 J1001.22 J1001.25 J1001.27 J1001.32 J1001.38 J1001.40 J1002.2 J1002.4 J1002.9 J1002.11 J1002.13 J1002.19 J1002.22 J1002.25 J1002.27 J1002.32 J1002.38 J1002.40 U1000.3(GND) U1001.2(GND) U1006.2(GND) ; port GND
AD_H_A: J1000.16 ; port AD_H_A
AD_H_B: J1001.16 ; port AD_H_B
AD_H_C: J1002.16 ; port AD_H_C
AD_L_A: J1000.15 ; port AD_L_A
AD_L_B: J1001.15 ; port AD_L_B
AD_L_C: J1002.15 ; port AD_L_C
GDAH: J1000.24 J1000.26 R1013.2 ; port GDAH
GDAL: J1000.21 J1000.23 R1013.1 ; port GDAL
GDBH: J1001.24 J1001.26 R1014.2 ; port GDBH
GDBL: J1001.21 J1001.23 R1014.1 ; port GDBL
GDCH: J1002.24 J1002.26 R1012.2 ; port GDCH
GDCL: J1002.21 J1002.23 R1012.1 ; port GDCL
LVSS_EN: J1000.28 J1001.28 J1002.28 ; port LVSS_EN
LVSS_IN_HS_A: J1000.30 R1017.1 ; port LVSS_IN_HS_A
LVSS_IN_HS_B: J1001.30 R1017.2 R1018.1 ; port LVSS_IN_HS_B
LVSS_IN_HS_C: J1002.30 R1018.2 ; port LVSS_IN_HS_C
LVSS_IN_LS_A: J1000.17 R1015.1 ; port LVSS_IN_LS_A
LVSS_IN_LS_B: J1001.17 R1015.2 R1016.1 ; port LVSS_IN_LS_B
LVSS_IN_LS_C: J1002.17 R1016.2 ; port LVSS_IN_LS_C
nFLT1_H_A: J1000.20 J1001.20 J1002.20 R1027.2 ; port nFLT1_H  [also labelled nFLT1_H_B, nFLT1_H_C]  [project net nFLT1_H]
nFLT1_L_A: J1000.29 J1001.29 J1002.29 R1030.2 ; port nFLT1_L  [also labelled nFLT1_L_B, nFLT1_L_C]  [project net nFLT1_L]
nFLT2_H: J1000.18 R1019.1 R1034.2 R1036.2 ; port nFLT2_H
nFLT2_H_B: J1001.18 R1020.1 R1034.1 ; port nFLT2_H2  [project net nFLT2_H2]
nFLT2_H_C: J1002.18 R1021.1 R1036.1 ; port nFLT2_H3  [project net nFLT2_H3]
nFLT2_L: J1000.31 R1022.2 R1040.2 R1042.2 ; port nFLT2_L
nFLT2_L_B: J1001.31 R1023.2 R1040.1 ; port nFLT2_L2  [project net nFLT2_L2]
nFLT2_L_C: J1002.31 R1024.2 R1042.1 ; port nFLT2_L3  [project net nFLT2_L3]
PGD1: R1009.1 U1006.1(A)  [project net PGD1_12]
PGD2: R1006.2 U1006.3(B)  [project net PGD2_12]
PGD3: R1010.1 U1006.6(C)  [project net PGD3_12]
PGD4: R1007.2 U1001.1(A)  [project net PGD4_12]
PGD5: R1011.1 U1001.3(B)  [project net PGD5_12]
PGD6: R1008.2 U1001.6(C)  [project net PGD6_12]
Power_EN_HS: J1000.36 J1001.36 J1002.36 ; port Power_EN_HS
Power_EN_LS: J1000.33 J1001.33 J1002.33 ; port Power_EN_LS
Power_good: U1000.4(Y) ; port Power_Good
PWM1_H: J1000.14 ; port PWM1_H
PWM1_L: J1000.12 ; port PWM1_L
PWM2_H: J1001.14 ; port PWM2_H
PWM2_L: J1001.12 ; port PWM2_L
PWM3_H: J1002.14 ; port PWM3_H
PWM3_L: J1002.12 ; port PWM3_L
UCC5890_CLK: J1000.10 J1001.10 J1002.10 ; port UCC5890_CLK
UCC5890_nCS: R1000.2 R1001.2 R1002.2 R1003.1 R1004.1 R1005.1 ; port UCC5890_nCS
UCC5890_SDI: J1000.5 J1001.5 J1002.5 ; port UCC5890_SDI
UCC5890_SDO: J1000.8 J1001.8 J1002.8 ; port UCC5890_SDO
NetJ1000_6: J1000.6 R1000.1
NetJ1000_7: J1000.7 R1003.2
NetJ1000_34: J1000.34 R1006.1
NetJ1000_35: J1000.35 R1009.2
NetJ1001_6: J1001.6 R1001.1
NetJ1001_7: J1001.7 R1004.2
NetJ1001_34: J1001.34 R1007.1
NetJ1001_35: J1001.35 R1010.2
NetJ1002_6: J1002.6 R1002.1
NetJ1002_7: J1002.7 R1005.2
NetJ1002_34: J1002.34 R1008.1
NetJ1002_35: J1002.35 R1011.2
NetU1000_1: U1000.1(A) U1006.4(Y)
NetU1000_2: U1000.2(B) U1001.4(Y)

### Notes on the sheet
- Interface to the GD board - PHASE A
- Interface to the GD board - PHASE B
- Interface to the GD board - PHASE C
- C3: pull up on all nfault
- Cable: FFSD-20-D-02.00-01-N
- (near R1012) Cable: FFSD-20-D-02.00-01-N
- C4: Power good signals from Magneto: OR gates for 6 signals.

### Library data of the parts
C1000-C1002 = CMP-0007173-4: CAP, CERM, 1000 pF, 50 V, +/- 5%, C0G/NP0, 0603; Manufacturer: MuRata; TaMin_C: -55°C; Polarized: N; SizeAreaWB_mm2: 4.68; Value1: Unknown; U/M: EA; Value: 1000pF; TaMax_C: 125°C; SizeZ_mm: 1; SizeX_mm: 1.6; SizeY_mm: 0.8; Value2: 50V; SizeArea_mm2: 1.28; AEC Category: Q200
J1000-J1002 = CMP-0092627-1: Connector Header Surface Mount 40 position 0.050" (1.27mm); Manufacturer: Samtec; SizeZ_mm: 5.59mm; ContactFinish: Gold,Nickel; Row_Count: 2; Conn Orientation: Vertical; Is Female: no; Conn Gender: Male
R1000-R1018 R1034 R1036 R1040 R1042 = CMP-0025697-4: RES, 0, 5%, 0.1 W, AEC-Q200 Grade 0, 0603; Manufacturer: Vishay-Dale; Power_W: 100mW; TempCo: 200 ppm/C; Value_Code: 0000; Value: 0; SizeX_mm: 1.6; SizeY_mm: 0.8; SizeZ_mm: 1; Value2: 0.1W; SizeArea_mm2: 1.28; AEC Qualified: Y; AEC Category: Q200; EIA_Code: E24; VDC_V: 75V
R1019-R1024 R1027 R1030 = CMP-0021998-4: as R905 on sheet thermal-management
U1000 = CMP-0051613-2: Single 2-Input Positive-OR Gate, DBV0005A (SOT-23-5); Manufacturer: Texas Instruments; Rating: Catalog; 3-State Output: No; Logic: True; VCC(Min)(V): 2; Voltage(Nom)(V): 3.3,5; F @ Nom Voltage(Max)(Mhz): 75; VCC(Max)(V): 5.5; Output Type: CMOS; Output Drive (IOL/IOH)(Max)(mA): 50/-50; tpd @ Nom Voltage(Max)(ns): 13,8.5; Gate Type: OR; Bits(#): 1; ICC @ Nom Voltage(Max)(mA): 0.01; AEC Category: Q200; AEC Qualified: N; CompType: IC; SizeAreaWB_mm2: 14.82; SizeArea_mm2: 8.12; SizeX_mm: 2.8; SizeY_mm: 2.9; SizeZ_mm: 1.45
U1001 U1006 = CMP-0051255-3: Single 3-Input Positive-OR Gate, DCK0006A (SOT-SC70-6); Manufacturer: Texas Instruments; Output Type: CMOS; Bits(#): 1; Input Type: CMOS/TTL; Technology Family: LVC; Schmitt Trigger: No; VCC(Max)(V): 5.5; Gate Type: OR; Rating: Catalog; Output Drive (IOL/IOH)(Max)(mA): 32/-32; ICC @ Nom Voltage(Max)(mA): 0.01; VCC(Min)(V): 1.65; F @ Nom Voltage(Max)(Mhz): 150; Logic: True; Voltage(Nom)(V): 1.8,2.5,3.3,5; tpd @ Nom Voltage(Max)(ns): 17.2,6.2,4.8,3.5; AEC Category: Q200; AEC Qualified: N; CompType: IC; SizeAreaWB_mm2: 9.3; SizeArea_mm2: 4.2; SizeX_mm: 2.1; SizeY_mm: 2.0; SizeZ_mm: 1.1

## Sheet controlSOM_Subsystem.SchDoc
size 431 x 279 mm; Date: Not shown in title block; ApprovedBy: Not shown in title block; CheckedBy: Not shown in title block; Author: Not shown in title block; CompanyName: Not shown in title block; Engineer: Not shown in title block; Organization: Not shown in title block; Address1: Not shown in title block; Address2: Not shown in title block; Address3: Not shown in title block; Address4: Not shown in title block; DocumentNumber: 18; Revision: Use project parameter SCH_Rev; SheetNumber: 16; SheetTotal: 19; PageSetup: Record=PageOptions¦CenterHorizontal=True¦CenterVertical=True¦PrintScale=1.00¦XCorrection=1.00¦YCorrection=1.00¦PrintKind=0¦BorderSize=5000000¦LeftOffset=0¦BottomOffset=0¦Orientation=2¦PaperLength=1000¦PaperWidth=1000¦Scale=100¦PaperSource=15¦PrintQuality=600¦MediaType=1¦DitherType=10¦PaperKind=Letter¦PrintScaleMode=1
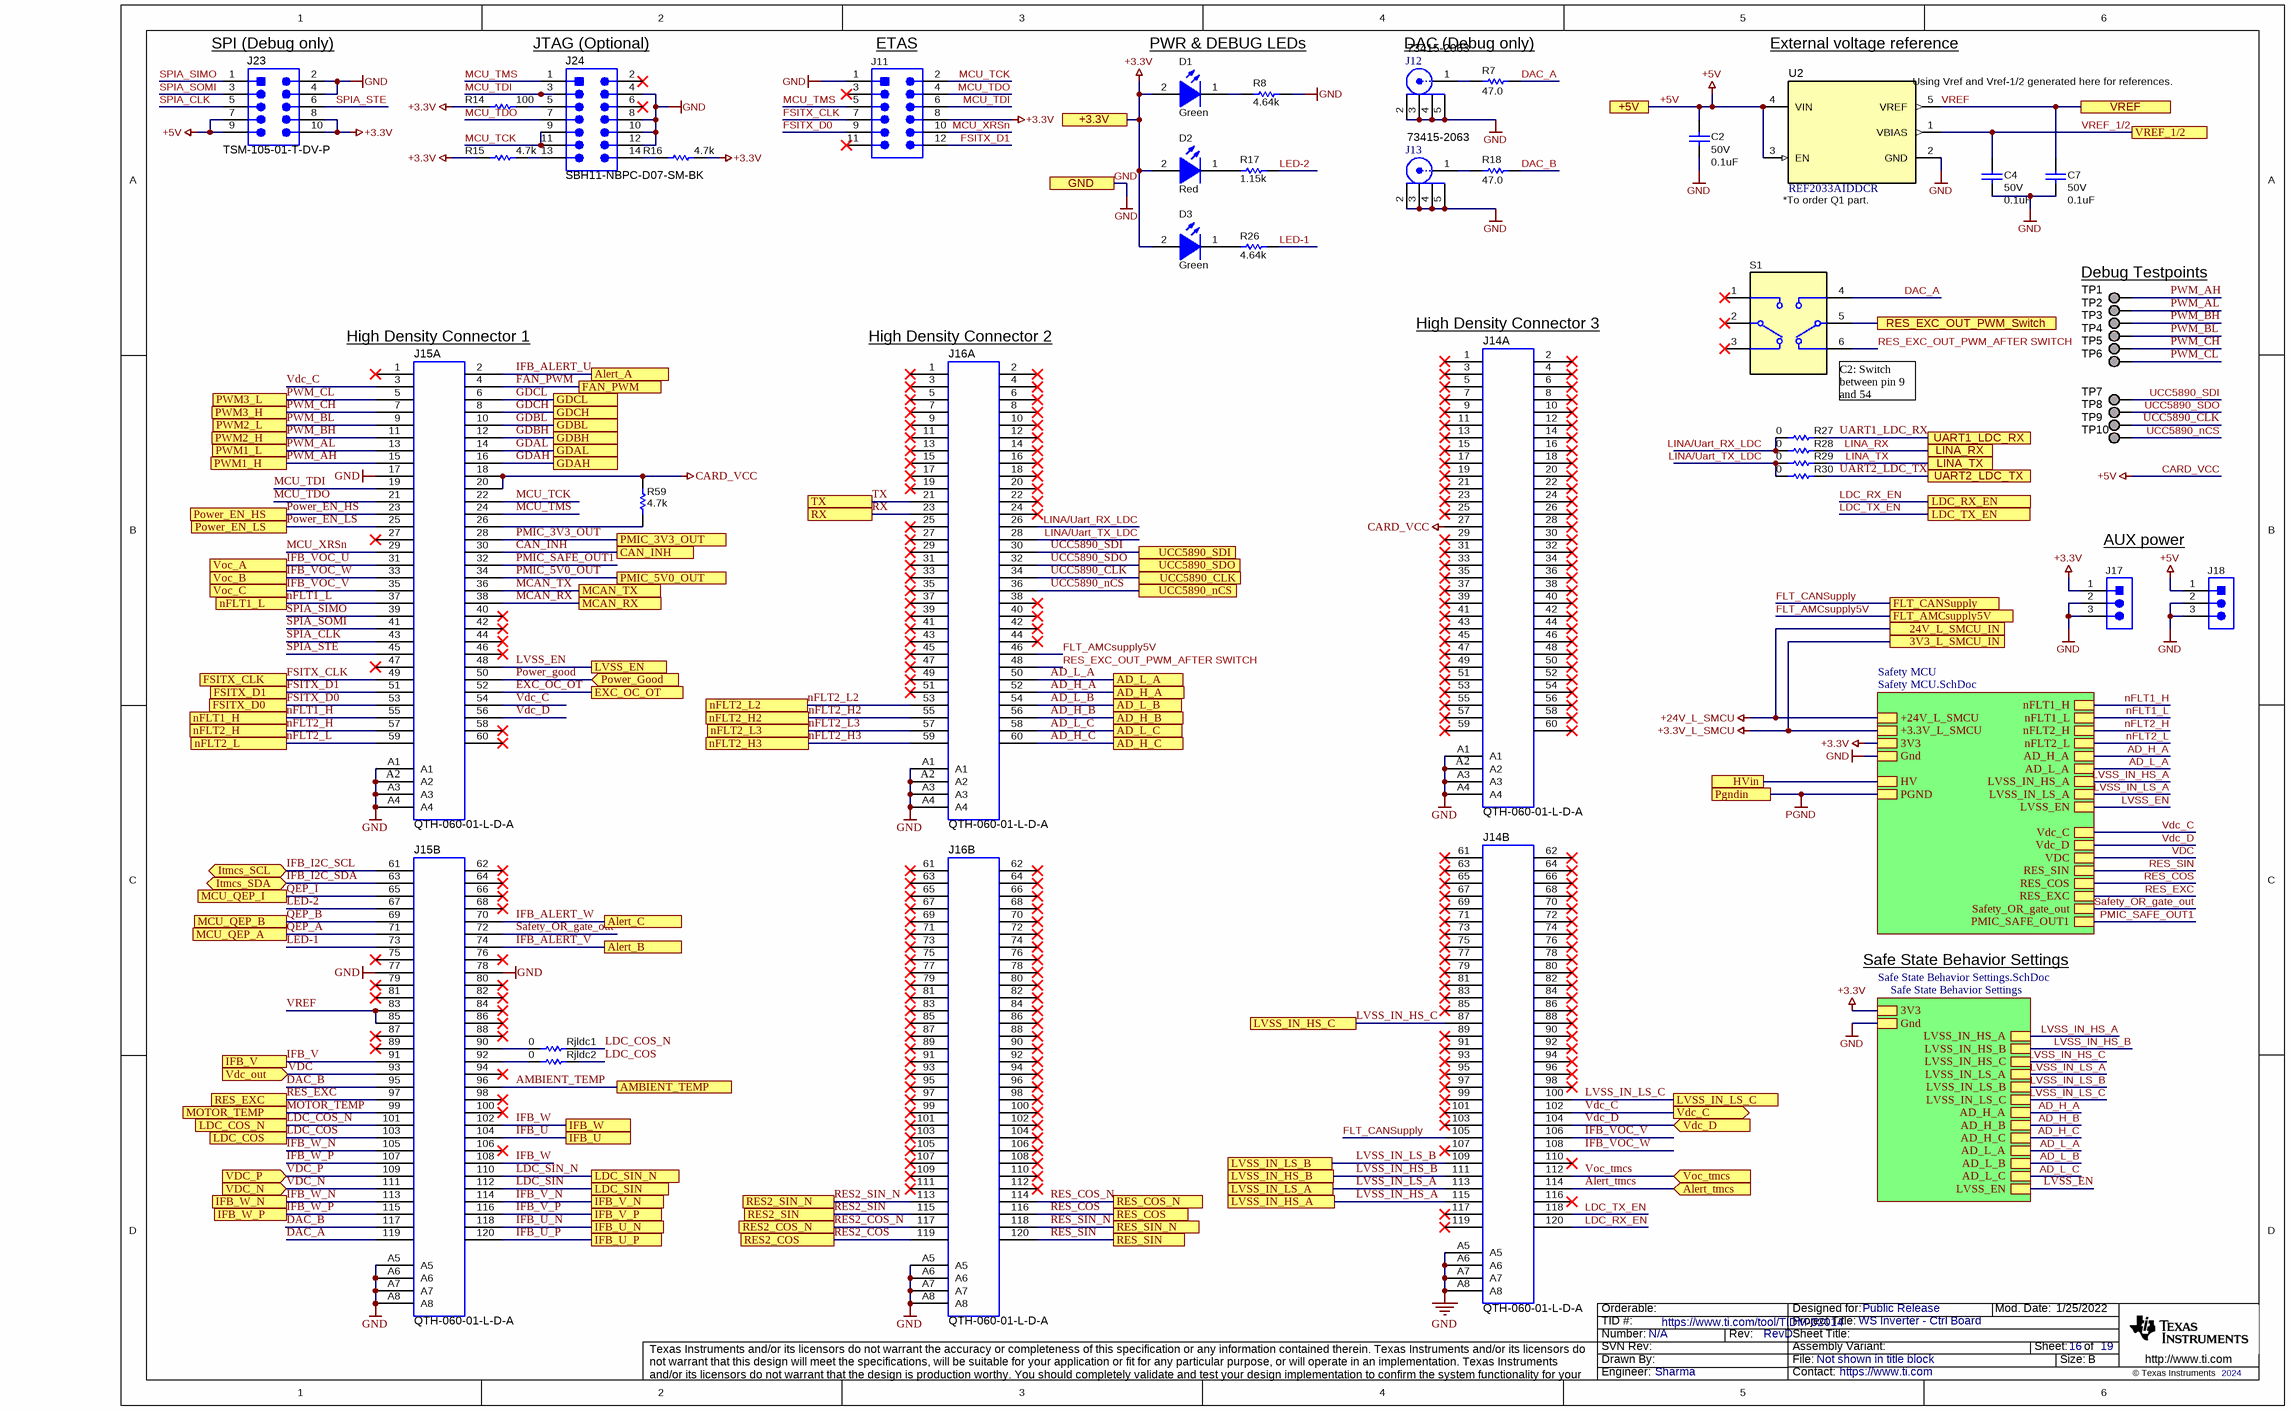
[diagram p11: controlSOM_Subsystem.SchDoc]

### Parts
C2  VDC_V: 50V  ValueDisplayed: 0.1uF  [0603]  (hidden comment: CGA3E2X7R1H104K080AA)
C4  VDC_V: 50V  ValueDisplayed: 0.1uF  [0603]  (hidden comment: CGA3E2X7R1H104K080AA)
C7  VDC_V: 50V  ValueDisplayed: 0.1uF  [0603]  (hidden comment: CGA3E2X7R1H104K080AA)
D1  value Green  [WL-SMCW_GREEN]  (hidden comment: 150060GS75000)
D2  value Red  [WL-SMCW_RED]  (hidden comment: 150060RS75000)
D3  value Green  [WL-SMCW_GREEN]  (hidden comment: 150060GS75000)
J11  TFM-106-02-S-D-A  [Samtec_TFM-106-02-x-D-A]  (value not drawn)
J12  73415-2063  [Molex_73415-2063]
J13  73415-2063  [Molex_73415-2063]
J14  QTH-060-01-L-D-A  [SAMTEC_QTH-060-01-L-D-A]  (parts A,B of 2)
J15  QTH-060-01-L-D-A  [SAMTEC_QTH-060-01-L-D-A]  (parts A,B of 2)
J16  QTH-060-01-L-D-A  [SAMTEC_QTH-060-01-L-D-A]  (parts A,B of 2)
J17  61300311121  [WURTH_61300311121]  (value not drawn)
J18  61300311121  [WURTH_61300311121]  (value not drawn)
J23  TSM-105-01-T-DV-P  [CONN_TSM-105-01-T-DV-P]
J24  SBH11-NBPC-D07-SM-BK  [Sullins_SBH11-xxxC-D07-SM-BK]
R7  ValueDisplayed: 47.0  [0603]  (hidden comment: CRCW060347R0FKEA)
R8  ValueDisplayed: 4.64k  [0603]  (hidden comment: CRCW06034K64FKEA)
R14  ValueDisplayed: 100  [0603]  (hidden comment: CRCW0603100RFKEA)
R15  ValueDisplayed: 4.7k  [0603]  (hidden comment: CRCW06034K70JNEA)
R16  ValueDisplayed: 4.7k  [0603]  (hidden comment: CRCW06034K70JNEA)
R17  ValueDisplayed: 1.15k  [0603]  (hidden comment: CRCW06031K15FKEA)
R18  ValueDisplayed: 47.0  [0603]  (hidden comment: CRCW060347R0FKEA)
R26  ValueDisplayed: 4.64k  [0603]  (hidden comment: CRCW06034K64FKEA)
R27  ValueDisplayed: 0  [0603]  (hidden comment: CRCW06030000Z0EA)
R28  ValueDisplayed: 0  [0603]  (hidden comment: CRCW06030000Z0EA)
R29  ValueDisplayed: 0  [0603]  (hidden comment: CRCW06030000Z0EA)
R30  ValueDisplayed: 0  [0603]  (hidden comment: CRCW06030000Z0EA)
R59  ValueDisplayed: 4.7k  [0603]  (hidden comment: CRCW06034K70JNEA)
Rjldc1  ValueDisplayed: 0  [0603]  (hidden comment: CRCW06030000Z0EA)
Rjldc2  ValueDisplayed: 0  [0603]  (hidden comment: CRCW06030000Z0EA)
S1  CAS-220TA  [SW_CAS-220TA]  (value not drawn)
TP1  RCU-0C  [TE_RCU]  (value not drawn)
TP2  RCU-0C  [TE_RCU]  (value not drawn)
TP3  RCU-0C  [TE_RCU]  (value not drawn)
TP4  RCU-0C  [TE_RCU]  (value not drawn)
TP5  RCU-0C  [TE_RCU]  (value not drawn)
TP6  RCU-0C  [TE_RCU]  (value not drawn)
TP7  RCU-0C  [TE_RCU]  (value not drawn)
TP8  RCU-0C  [TE_RCU]  (value not drawn)
TP9  RCU-0C  [TE_RCU]  (value not drawn)
TP10  RCU-0C  [TE_RCU]  (value not drawn)
U2  REF2033AIDDCR  [DDC0005A_N]

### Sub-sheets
Safe State Behavior Settings = Safe State Behavior Settings.SchDoc: 3V3, Gnd, LVSS_IN_HS_A, LVSS_IN_HS_B, LVSS_IN_HS_C, LVSS_IN_LS_A, LVSS_IN_LS_B, LVSS_IN_LS_C, AD_H_A, AD_H_B, AD_H_C, AD_L_A, AD_L_B, AD_L_C, LVSS_EN
Safety MCU = Safety MCU.SchDoc: +24V_L_SMCU, +3.3V_L_SMCU, 3V3, Gnd, HV, PGND, nFLT1_H, nFLT1_L, nFLT2_H, nFLT2_L, AD_H_A, AD_L_A, LVSS_IN_HS_A, LVSS_IN_LS_A, LVSS_EN, Vdc_C, Vdc_D, VDC, RES_SIN, RES_COS, RES_EXC, Safety_OR_gate_out, PMIC_SAFE_OUT1

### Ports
3V3_L_SMCU_IN, 24V_L_SMCU_IN, +3.3V, +5V, AD_H_A, AD_H_B, AD_H_C, AD_L_A, AD_L_B, AD_L_C, Alert_A, Alert_B, Alert_C, Alert_tmcs (in), AMBIENT_TEMP, CAN_INH, EXC_OC_OT, FAN_PWM, FLT_AMCsupply5V, FLT_CANSupply, FSITX_CLK, FSITX_D0, FSITX_D1, GDAH, GDAL, GDBH, GDBL, GDCH, GDCL, GND, HVin, IFB_U, IFB_U_N, IFB_U_P, IFB_V, IFB_V_N, IFB_V_P, IFB_W, IFB_W_N, IFB_W_P, Itmcs_SCL (bidir), Itmcs_SDA (bidir), LDC_COS, LDC_COS_N, LDC_RX_EN, LDC_SIN, LDC_SIN_N, LDC_TX_EN, LINA_RX, LINA_TX, LVSS_EN, LVSS_IN_HS_A, LVSS_IN_HS_B, LVSS_IN_HS_C, LVSS_IN_LS_A, LVSS_IN_LS_B, LVSS_IN_LS_C, MCAN_RX, MCAN_TX, MCU_QEP_A, MCU_QEP_B, MCU_QEP_I, MOTOR_TEMP, nFLT1_H, nFLT1_L, nFLT2_H, nFLT2_H2, nFLT2_H3, nFLT2_L, nFLT2_L2, nFLT2_L3, Pgndin, PMIC_3V3_OUT, PMIC_5V0_OUT, Power_EN_HS, Power_EN_LS, Power_Good (in), PWM1_H, PWM1_L, PWM2_H, PWM2_L, PWM3_H, PWM3_L, RES2_COS, RES2_COS_N, RES2_SIN, RES2_SIN_N, RES_COS, RES_COS_N, RES_EXC, RES_EXC_OUT_PWM_Switch, RES_SIN, RES_SIN_N, RX, TX, UART1_LDC_RX, UART2_LDC_TX, UCC5890_CLK, UCC5890_nCS, UCC5890_SDI, UCC5890_SDO, Vdc_C (out), Vdc_D (in), VDC_N (in), Vdc_out (in), VDC_P (in), Voc_A, Voc_B, Voc_C, Voc_tmcs (in), VREF, VREF_1/2

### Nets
+3.3V: D1.2(A) D2.2(A) D3.2(A) J11.8 J17.1 J23.8 J23.10 R14.1 R15.1 R16.2 ; port +3.3V, sheet Safety MCU/3V3, sheet Safe State Behavior Settings/3V3
+3.3V_L_SMCU: port 3V3_L_SMCU_IN, sheet Safety MCU/+3.3V_L_SMCU  [project net 3V3_L_SMCU_IN]
+5V: C2.1 J14.27 J15.18 J15.20 J18.1 J23.7 J23.9 R59.2 U2.3(EN) U2.4(VIN) ; port +5V  [also labelled CARD_VCC]
+24V_L_SMCU: port 24V_L_SMCU_IN, sheet Safety MCU/+24V_L_SMCU  [project net 24V_L_SMCU_IN]
GND: C2.2 C4.2 C7.2 J11.1 J12.2 J12.3 J12.4 J12.5 J13.2 J13.3 J13.4 J13.5 J14.A1 J14.A2 J14.A3 J14.A4 J14.A5 J14.A6 J14.A7 J14.A8 J15.17 J15.77 J15.78 J15.A1 J15.A2 J15.A3 J15.A4 J15.A5 J15.A6 J15.A7 J15.A8 J16.A1 J16.A2 J16.A3 J16.A4 J16.A5 J16.A6 J16.A7 J16.A8 J17.2 J17.3 J18.2 J18.3 J23.2 J23.4 J24.4 J24.8 J24.10 J24.12 R8.1 U2.2(GND) ; port GND, sheet Safety MCU/Gnd, sheet Safe State Behavior Settings/Gnd
HV: port HVin, sheet Safety MCU/HV
PGND: port Pgndin, sheet Safety MCU/PGND  [project net Pgndin]
VREF: C7.1 J15.83 J15.85 U2.5(VREF) ; port VREF
VREF_1/2: C4.1 U2.1(VBIAS) ; port VREF_1/2
AD_H_A: J16.52 ; port AD_H_A, sheet Safety MCU/AD_H_A, sheet Safe State Behavior Settings/AD_H_A
AD_H_B: J16.56 ; port AD_H_B, sheet Safe State Behavior Settings/AD_H_B
AD_H_C: J16.60 ; port AD_H_C, sheet Safe State Behavior Settings/AD_H_C
AD_L_A: J16.50 ; port AD_L_A, sheet Safety MCU/AD_L_A, sheet Safe State Behavior Settings/AD_L_A
AD_L_B: J16.54 ; port AD_L_B, sheet Safe State Behavior Settings/AD_L_B
AD_L_C: J16.58 ; port AD_L_C, sheet Safe State Behavior Settings/AD_L_C
Alert_tmcs: J14.114 ; port Alert_tmcs
AMBIENT_TEMP: J15.96 ; port AMBIENT_TEMP
CAN_INH: J15.30 ; port CAN_INH
DAC_A: J15.119 R7.2 S1.4  [project net DAC_A_16]
DAC_B: J15.95 J15.117 R18.2  [project net DAC_B_16]
EXC_OC_OT: J15.52 ; port EXC_OC_OT
FAN_PWM: J15.4 ; port FAN_PWM
FLT_AMCsupply5V: J16.46 ; port FLT_AMCsupply5V
FLT_CANSupply: J14.105 ; port FLT_CANSupply
FSITX_CLK: J11.7 J15.49 ; port FSITX_CLK
FSITX_D0: J11.9 J15.53 ; port FSITX_D0
FSITX_D1: J11.12 J15.51 ; port FSITX_D1
GDAH: J15.16 ; port GDAH
GDAL: J15.14 ; port GDAL
GDBH: J15.12 ; port GDBH
GDBL: J15.10 ; port GDBL
GDCH: J15.8 ; port GDCH
GDCL: J15.6 ; port GDCL
IFB_ALERT_U: J15.2 ; port Alert_A  [project net Alert_A]
IFB_ALERT_V: J15.74 ; port Alert_B  [project net Alert_B]
IFB_ALERT_W: J15.70 ; port Alert_C  [project net Alert_C]
IFB_I2C_SCL: J15.61 ; port Itmcs_SCL
IFB_I2C_SDA: J15.63 ; port Itmcs_SDA
IFB_U: J15.104 ; port IFB_U
IFB_U_N: J15.118 ; port IFB_U_N
IFB_U_P: J15.120 ; port IFB_U_P
IFB_V: J15.91 ; port IFB_V
IFB_V_N: J15.114 ; port IFB_V_N
IFB_V_P: J15.116 ; port IFB_V_P
IFB_VOC_U: J15.31 ; port Voc_A
IFB_VOC_V: J14.106 J15.35 ; port Voc_C
IFB_VOC_W: J14.108 J15.33 ; port Voc_B
IFB_W: J15.102 J15.108 ; port IFB_W
IFB_W_N: J15.105 J15.113 ; port IFB_W_N
IFB_W_P: J15.107 J15.115 ; port IFB_W_P
LDC_COS: J15.103 Rjldc2.2 ; port LDC_COS
LDC_COS_N: J15.101 Rjldc1.2 ; port LDC_COS_N
LDC_RX_EN: J14.120 ; port LDC_RX_EN
LDC_SIN: J15.112 ; port LDC_SIN
LDC_SIN_N: J15.110 ; port LDC_SIN_N
LDC_TX_EN: J14.118 ; port LDC_TX_EN
LED-1: J15.73 R26.1  [project net LED-1_16]
LED-2: J15.67 R17.1  [project net LED-2_16]
LINA/Uart_RX_LDC: J16.26 R27.1 R28.1  [project net LINA/Uart_RX_LDC_16]
LINA/Uart_TX_LDC: J16.28 R29.1 R30.1  [project net LINA/Uart_TX_LDC_16]
LINA_RX: R28.2 ; port LINA_RX
LINA_TX: R29.2 ; port LINA_TX
LVSS_EN: J15.48 ; port LVSS_EN, sheet Safety MCU/LVSS_EN, sheet Safe State Behavior Settings/LVSS_EN
LVSS_IN_HS_A: J14.115 ; port LVSS_IN_HS_A, sheet Safety MCU/LVSS_IN_HS_A, sheet Safe State Behavior Settings/LVSS_IN_HS_A
LVSS_IN_HS_B: J14.111 ; port LVSS_IN_HS_B, sheet Safe State Behavior Settings/LVSS_IN_HS_B
LVSS_IN_HS_C: J14.87 ; port LVSS_IN_HS_C, sheet Safe State Behavior Settings/LVSS_IN_HS_C
LVSS_IN_LS_A: J14.113 ; port LVSS_IN_LS_A, sheet Safety MCU/LVSS_IN_LS_A, sheet Safe State Behavior Settings/LVSS_IN_LS_A
LVSS_IN_LS_B: J14.109 ; port LVSS_IN_LS_B, sheet Safe State Behavior Settings/LVSS_IN_LS_B
LVSS_IN_LS_C: J14.100 ; port LVSS_IN_LS_C, sheet Safe State Behavior Settings/LVSS_IN_LS_C
MCAN_RX: J15.38 ; port MCAN_RX
MCAN_TX: J15.36 ; port MCAN_TX
MCU_TCK: J11.2 J15.22 J24.9 J24.11  [project net MCU_TCK_16]
MCU_TDI: J11.6 J15.19 J24.3  [project net MCU_TDI_16]
MCU_TDO: J11.4 J15.21 J24.7  [project net MCU_TDO_16]
MCU_TMS: J11.5 J15.24 J24.1  [project net MCU_TMS_16]
MCU_XRSn: J11.10 J15.29  [project net MCU_XRSn_16]
MOTOR_TEMP: J15.99 ; port MOTOR_TEMP
nFLT1_H: J15.55 ; port nFLT1_H, sheet Safety MCU/nFLT1_H
nFLT1_L: J15.37 ; port nFLT1_L, sheet Safety MCU/nFLT1_L
nFLT2_H: J15.57 ; port nFLT2_H, sheet Safety MCU/nFLT2_H
nFLT2_H2: J16.55 ; port nFLT2_H2
nFLT2_H3: J16.59 ; port nFLT2_H3
nFLT2_L: J15.59 ; port nFLT2_L, sheet Safety MCU/nFLT2_L
nFLT2_L2: J16.53 ; port nFLT2_L2
nFLT2_L3: J16.57 ; port nFLT2_L3
PMIC_3V3_OUT: J15.28 ; port PMIC_3V3_OUT
PMIC_5V0_OUT: J15.34 ; port PMIC_5V0_OUT
PMIC_SAFE_OUT1: J15.32 ; sheet Safety MCU/PMIC_SAFE_OUT1
Power_EN_HS: J15.23 ; port Power_EN_HS
Power_EN_LS: J15.25 ; port Power_EN_LS
Power_good: J15.50 ; port Power_Good
PWM_AH: J15.15 TP1.1 ; port PWM1_H  [project net PWM1_H]
PWM_AL: J15.13 TP2.1 ; port PWM1_L  [project net PWM1_L]
PWM_BH: J15.11 TP3.1 ; port PWM2_H  [project net PWM2_H]
PWM_BL: J15.9 TP4.1 ; port PWM2_L  [project net PWM2_L]
PWM_CH: J15.7 TP5.1 ; port PWM3_H  [project net PWM3_H]
PWM_CL: J15.5 TP6.1 ; port PWM3_L  [project net PWM3_L]
QEP_A: J15.71 ; port MCU_QEP_A  [project net MCU_QEP_A]
QEP_B: J15.69 ; port MCU_QEP_B  [project net MCU_QEP_B]
QEP_I: J15.65 ; port MCU_QEP_I  [project net MCU_QEP_I]
RES2_COS: J16.119 ; port RES2_COS
RES2_COS_N: J16.117 ; port RES2_COS_N
RES2_SIN: J16.115 ; port RES2_SIN
RES2_SIN_N: J16.113 ; port RES2_SIN_N
RES_COS: J16.116 ; port RES_COS, sheet Safety MCU/RES_COS
RES_COS_N: J16.114 ; port RES_COS_N
RES_EXC: J15.97 ; port RES_EXC, sheet Safety MCU/RES_EXC
RES_EXC_OUT_PWM: S1.5 ; port RES_EXC_OUT_PWM_Switch
RES_EXC_OUT_PWM_AFTER SWITCH: J16.48 S1.6  [project net RES_EXC_OUT_PWM_AFTER SWITCH_16]
RES_SIN: J16.120 ; port RES_SIN, sheet Safety MCU/RES_SIN
RES_SIN_N: J16.118 ; port RES_SIN_N
RX: J16.23 ; port RX
Safety_OR_gate_out: J15.72 ; sheet Safety MCU/Safety_OR_gate_out
SPIA_CLK: J15.43 J23.5  [project net SPIA_CLK_16]
SPIA_SIMO: J15.39 J23.1  [project net SPIA_SIMO_16]
SPIA_SOMI: J15.41 J23.3  [project net SPIA_SOMI_16]
SPIA_STE: J15.45 J23.6  [project net SPIA_STE_16]
TX: J16.21 ; port TX
UART1_LDC_RX: R27.2 ; port UART1_LDC_RX
UART2_LDC_TX: R30.2 ; port UART2_LDC_TX
UCC5890_CLK: J16.34 TP9.1 ; port UCC5890_CLK
UCC5890_nCS: J16.36 TP10.1 ; port UCC5890_nCS
UCC5890_SDI: J16.30 TP7.1 ; port UCC5890_SDI
UCC5890_SDO: J16.32 TP8.1 ; port UCC5890_SDO
VDC: J15.93 ; port Vdc_out, sheet Safety MCU/VDC
Vdc_C: J14.102 J15.3 J15.54 ; port Vdc_C, sheet Safety MCU/Vdc_C
Vdc_D: J14.104 J15.56 ; port Vdc_D, sheet Safety MCU/Vdc_D
VDC_N: J15.111 ; port VDC_N
VDC_P: J15.109 ; port VDC_P
Voc_tmcs: J14.112 ; port Voc_tmcs
NetD1_1: D1.1(K) R8.2
NetD2_1: D2.1(K) R17.2
NetD3_1: D3.1(K) R26.2
NetJ12_1: J12.1 R7.1
NetJ13_1: J13.1 R18.1
NetJ15_26: J15.26 R59.1
NetJ15_90: J15.90 Rjldc1.1
NetJ15_92: J15.92 Rjldc2.1
NetJ24_5: J24.5 R14.2
NetJ24_13: J24.13 R15.2
NetJ24_14: J24.14 R16.1

Not connected (* = marked no-connect by the designer): J11 3* 11*; J14 1* 2* 3* 4* 5* 6* 7* 8* 9* 10* 11* 12* 13* 14* 15* 16* 17* 18* 19* 20* 21* 22* 23* 24* 25* 26* 28* 29* 30* 31* 32* 33* 34* 35* 36* 37* 38* 39* 40* 41* 42* 43* 44* 45* 46* 47* 48* 49* 50* 51* 52* 53* 54* 55* 56* 57* 58* 59* 60* 61* 62* 63* 64* 65* 66* 67* 68* 69* 70* 71* 72* 73* 74* 75* 76* 77* 78* 79* 80* 81* 82* 83* 84* 85* 86* 88* 89* 90* 91* 92* 93* 94* 95* 96* 97* 98* 99* 101* 103* 107* 110* 116* 117* 119*; J15 1* 27* 40* 42* 44* 46* 47* 58* 60* 62* 64* 66* 68* 75* 76* 79* 80* 81* 82* 84* 86* 87* 88* 89* 94* 98* 100* 106*; J16 1* 2* 3* 4* 5* 6* 7* 8* 9* 10* 11* 12* 13* 14* 15* 16* 17* 18* 19* 20* 22* 24* 25* 27* 29* 31* 33* 35* 37* 38* 39* 40* 41* 42* 43* 44* 45* 47* 49* 51* 61* 62* 63* 64* 65* 66* 67* 68* 69* 70* 71* 72* 73* 74* 75* 76* 77* 78* 79* 80* 81* 82* 83* 84* 85* 86* 87* 88* 89* 90* 91* 92* 93* 94* 95* 96* 97* 98* 99* 100* 101* 102* 103* 104* 105* 106* 107* 108* 109* 110* 111* 112*; J24 2* 6*; S1 1* 2* 3*

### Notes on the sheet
- (near J23) SPI (Debug only)
- (near J24) JTAG (Optional)
- (near J11) ETAS
- PWR & DEBUG LEDs
- DAC (Debug only)
- External voltage reference
- (near U2) Using Vref and Vref-1/2 generated here for references.
- (near U2) *To order Q1 part.
- (near TP1) Debug Testpoints
- (near J15) High Density Connector 1
- (near J16) High Density Connector 2
- (near J14) High Density Connector 3
- (near S1) C2: Switch between pin 9 and 54
- AUX power
- Safe State Behavior Settings

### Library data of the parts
C2 C4 C7 = CMP-0007078-4: as C15 on sheet Current Sense Connector
D1 D3 = CMP-0002905-2: LED, Green, SMD; Manufacturer: Wurth Elektronik; Type: InGaN; Vf_V: 3.2V; Io_A: 20mA; Tjmax_C: 85°C; Value1: W; Angle: 140
D2 = CMP-0002947-3: LED, Red, SMD; Manufacturer: Wurth Elektronik; Value1: 0.072W; Vf_V: 2V; Angle: 140; Tjmax_C: 85°C; Type: AlInGaP; Vr_V: 5V; Io_A: 30mA; Power_TotalModule: 72mW
J11 = CMP-0075601-2: Header(Shrouded), 1.27mm, 6x2, Tin, SMT; Manufacturer: Samtec; Pitch_mm: 1.27; Gender: Male; Cert_CSA: Y; Current_A: 3.2A; Voltage_V: 250V; ContactFinish: Gold; Row_Count: 2
J12 J13 = CMP-0055256-1: MMCX JACK, 50 Ohm, Gold, SMT; Manufacturer: Molex; CNHeader: FALSE; Gender: Female; Row_Count: 1; Pitch_mm: 2.64
J14-J16 = CMP-0056023-2: Socket, 0.5MM, 60x2, Gold, SMT; Manufacturer: Samtec; Green_Lifecycle: Not Set; Green_REACh: Incomplete
J17 J18 = CMP-0054796-4: Header, 2.54 mm, 3x1, Gold, TH; Manufacturer: Wurth Elektronik; Green_Lifecycle: Active; Green_REACh: Passed; CT: FALSE; CNHeader: TRUE
J23 = CMP-0075437-2: Header, 100mil, 5x2, Tin, SMT; Manufacturer: Samtec; Green_REACh: Passed; Green_Lifecycle: Active
J24 = CMP-0054738-2: Header(shrouded), 2.54mm, 7x2, Gold, SMT; Manufacturer: Sullins Connector Solutions; Current_A: 3A; Shrouded: Y; Gender: Male; Row_Count: 2; RowSpacing_mm: 2.54
R7 R18 = CMP-0081280-1: as R904 on sheet thermal-management
R8 R26 = CMP-0022455-4: RES, 4.64 k, 1%, 0.1 W, AEC-Q200 Grade 0, 0603; Manufacturer: Vishay-Dale; Power_W: 100mW; TempCo: 100 ppm/C; Value_Code: 4k64; Value: 4.64k; SizeX_mm: 1.6; SizeY_mm: 0.8; SizeZ_mm: 1; Value2: 0.1W; SizeArea_mm2: 1.28; AEC Qualified: Y; VDC_V: 75V; AEC Category: Q200; AEC Grade: 0; EIA_Code: E96
R14 = CMP-0021991-4: RES, 100, 1%, 0.1 W, AEC-Q200 Grade 0, 0603; Manufacturer: Vishay-Dale; Power_W: 100mW; TempCo: 100 ppm/C; Value_Code: 100R; Value: 100; EIA_Code: E96; SizeX_mm: 1.6; SizeY_mm: 0.8; SizeZ_mm: 1; Value2: 0.1W; SizeArea_mm2: 1.28; AEC Qualified: Y; AEC Grade: 0; AEC Category: Q200; VDC_V: 75V
R15 R16 R59 = CMP-0025817-4: RES, 4.7 k, 5%, 0.1 W, AEC-Q200 Grade 0, 0603; Manufacturer: Vishay-Dale; Power_W: 100mW; TempCo: 200 ppm/C; Value_Code: 4k70; Value: 4.7k; SizeX_mm: 1.6; SizeY_mm: 0.8; SizeZ_mm: 1; Value2: 0.1W; SizeArea_mm2: 1.28; AEC Qualified: Y; VDC_V: 75V; AEC Category: Q200; AEC Grade: 0; EIA_Code: E24
R17 = CMP-0022115-4: RES, 1.15 k, 1%, 0.1 W, AEC-Q200 Grade 0, 0603; Manufacturer: Vishay-Dale; Power_W: 100mW; TempCo: 100 ppm/C; Value_Code: 1k15; Value: 1.15k; SizeX_mm: 1.6; SizeY_mm: 0.8; SizeZ_mm: 1; Value2: 0.1W; SizeArea_mm2: 1.28; AEC Qualified: Y; VDC_V: 75V; AEC Category: Q200; AEC Grade: 0; EIA_Code: E96
R27-R30 Rjldc1 Rjldc2 = CMP-0025697-4: RES, 0, 5%, 0.1 W, AEC-Q200 Grade 0, 0603; Manufacturer: Vishay-Dale; Value_Code: 0000; SizeArea_mm2: 1.28; AEC Qualified: Y; AEC Category: Q200; Value: 0; SizeZ_mm: 1; SizeY_mm: 0.8; Power_W: 100mW; Value2: 0.1W; SizeX_mm: 1.6; EIA_Code: E24; TempCo: 200 ppm/C; VDC_V: 75V
S1 = CMP-0002123-2: SLIDE SWITCH DPDT  .1A, SMT; Manufacturer: Copal Electronics; CurrentRating_mA: 100A; SwitchFunction: On-On; VDC_V: 6V; PositionCount: 2
TP1-TP10 = CMP-0067620-1: as TP900 on sheet thermal-management
U2 = CMP-0066190-1: Low-Drift, Low-Power, Dual-Output VREF and VREF/2 Voltage Reference, DDC0005A (SOT-23-T-5); Alternate PartNumber: REF2033AIDDCT; Alternate Manufacturer: Texas Instruments; SizeAreaWB_mm2: 14.82; U/M: EA; SizeZ_mm: 1.1; SizeX_mm: 2.8; SizeY_mm: 2.9; SizeArea_mm2: 8.12; CompType: IC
